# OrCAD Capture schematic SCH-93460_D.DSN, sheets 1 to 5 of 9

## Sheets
1 09. CAN, RF GPO: size C; title: KW47-LOC; rev: D; company: NXP Semiconductors; note: SCH-93460 PDF: SPF-93460; note: 6501 William Cannon Drive West; note: Austin, TX 78735-8598
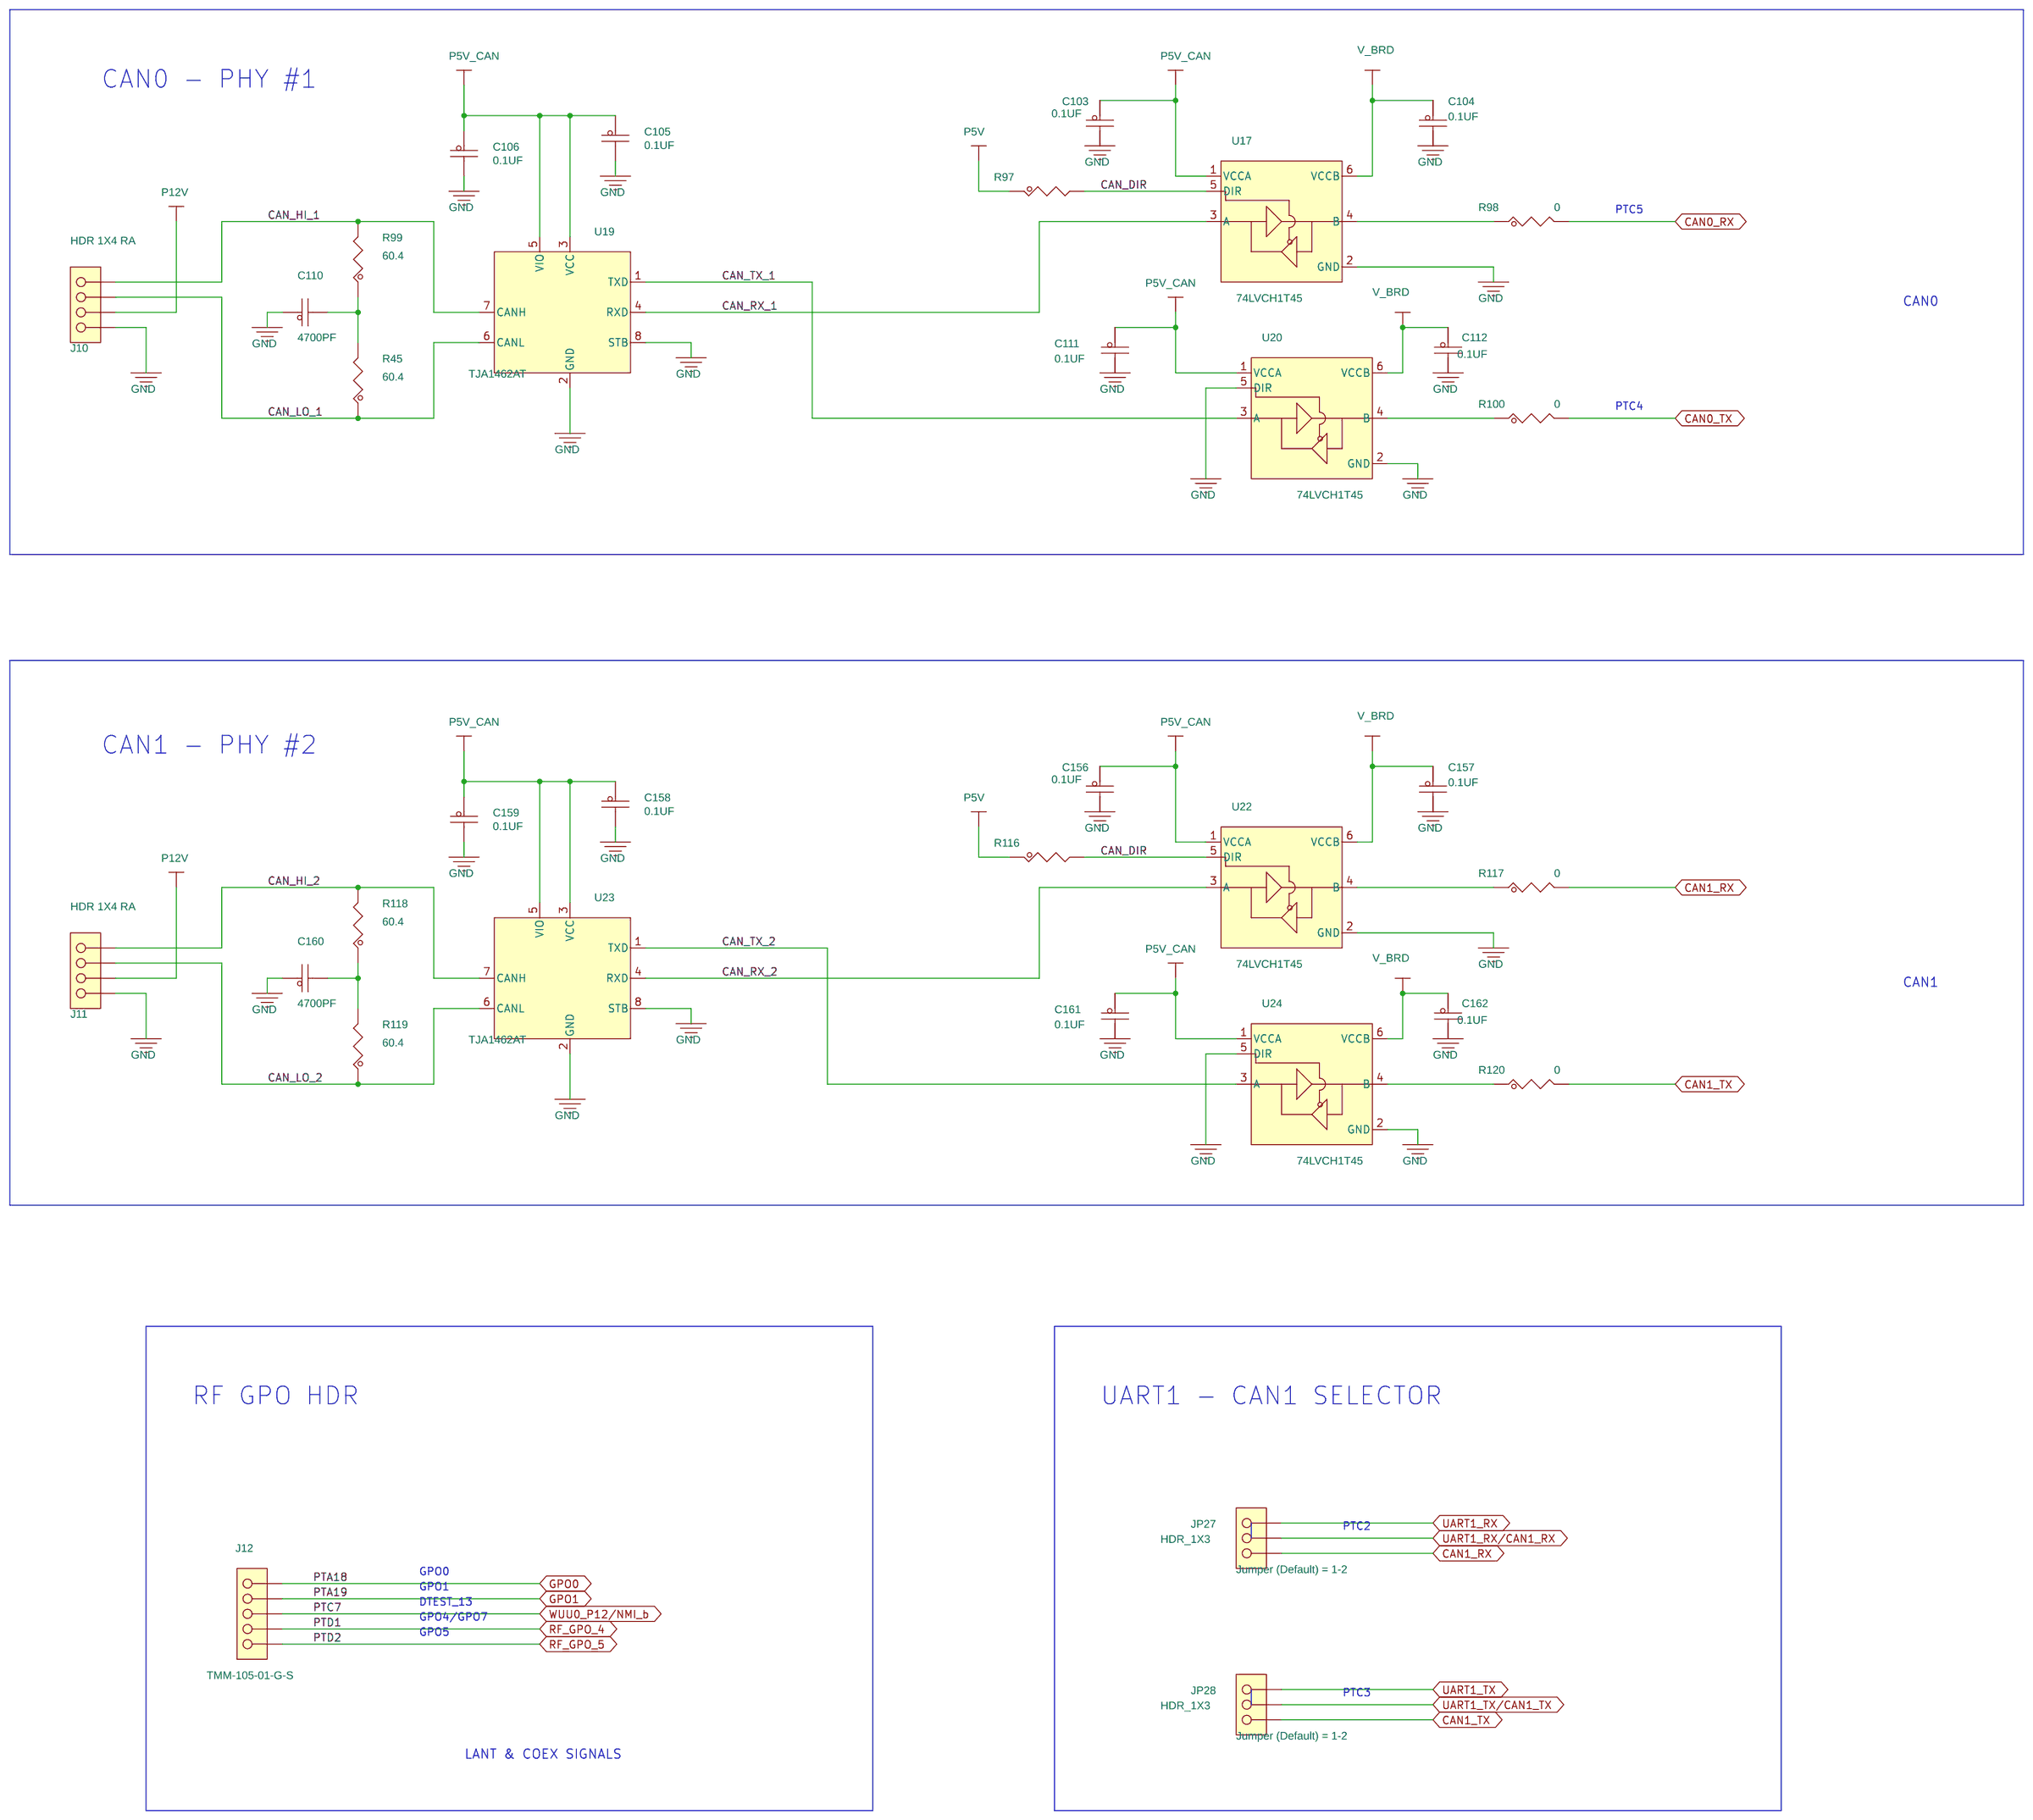
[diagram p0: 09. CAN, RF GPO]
2 01. TITLE PAGE
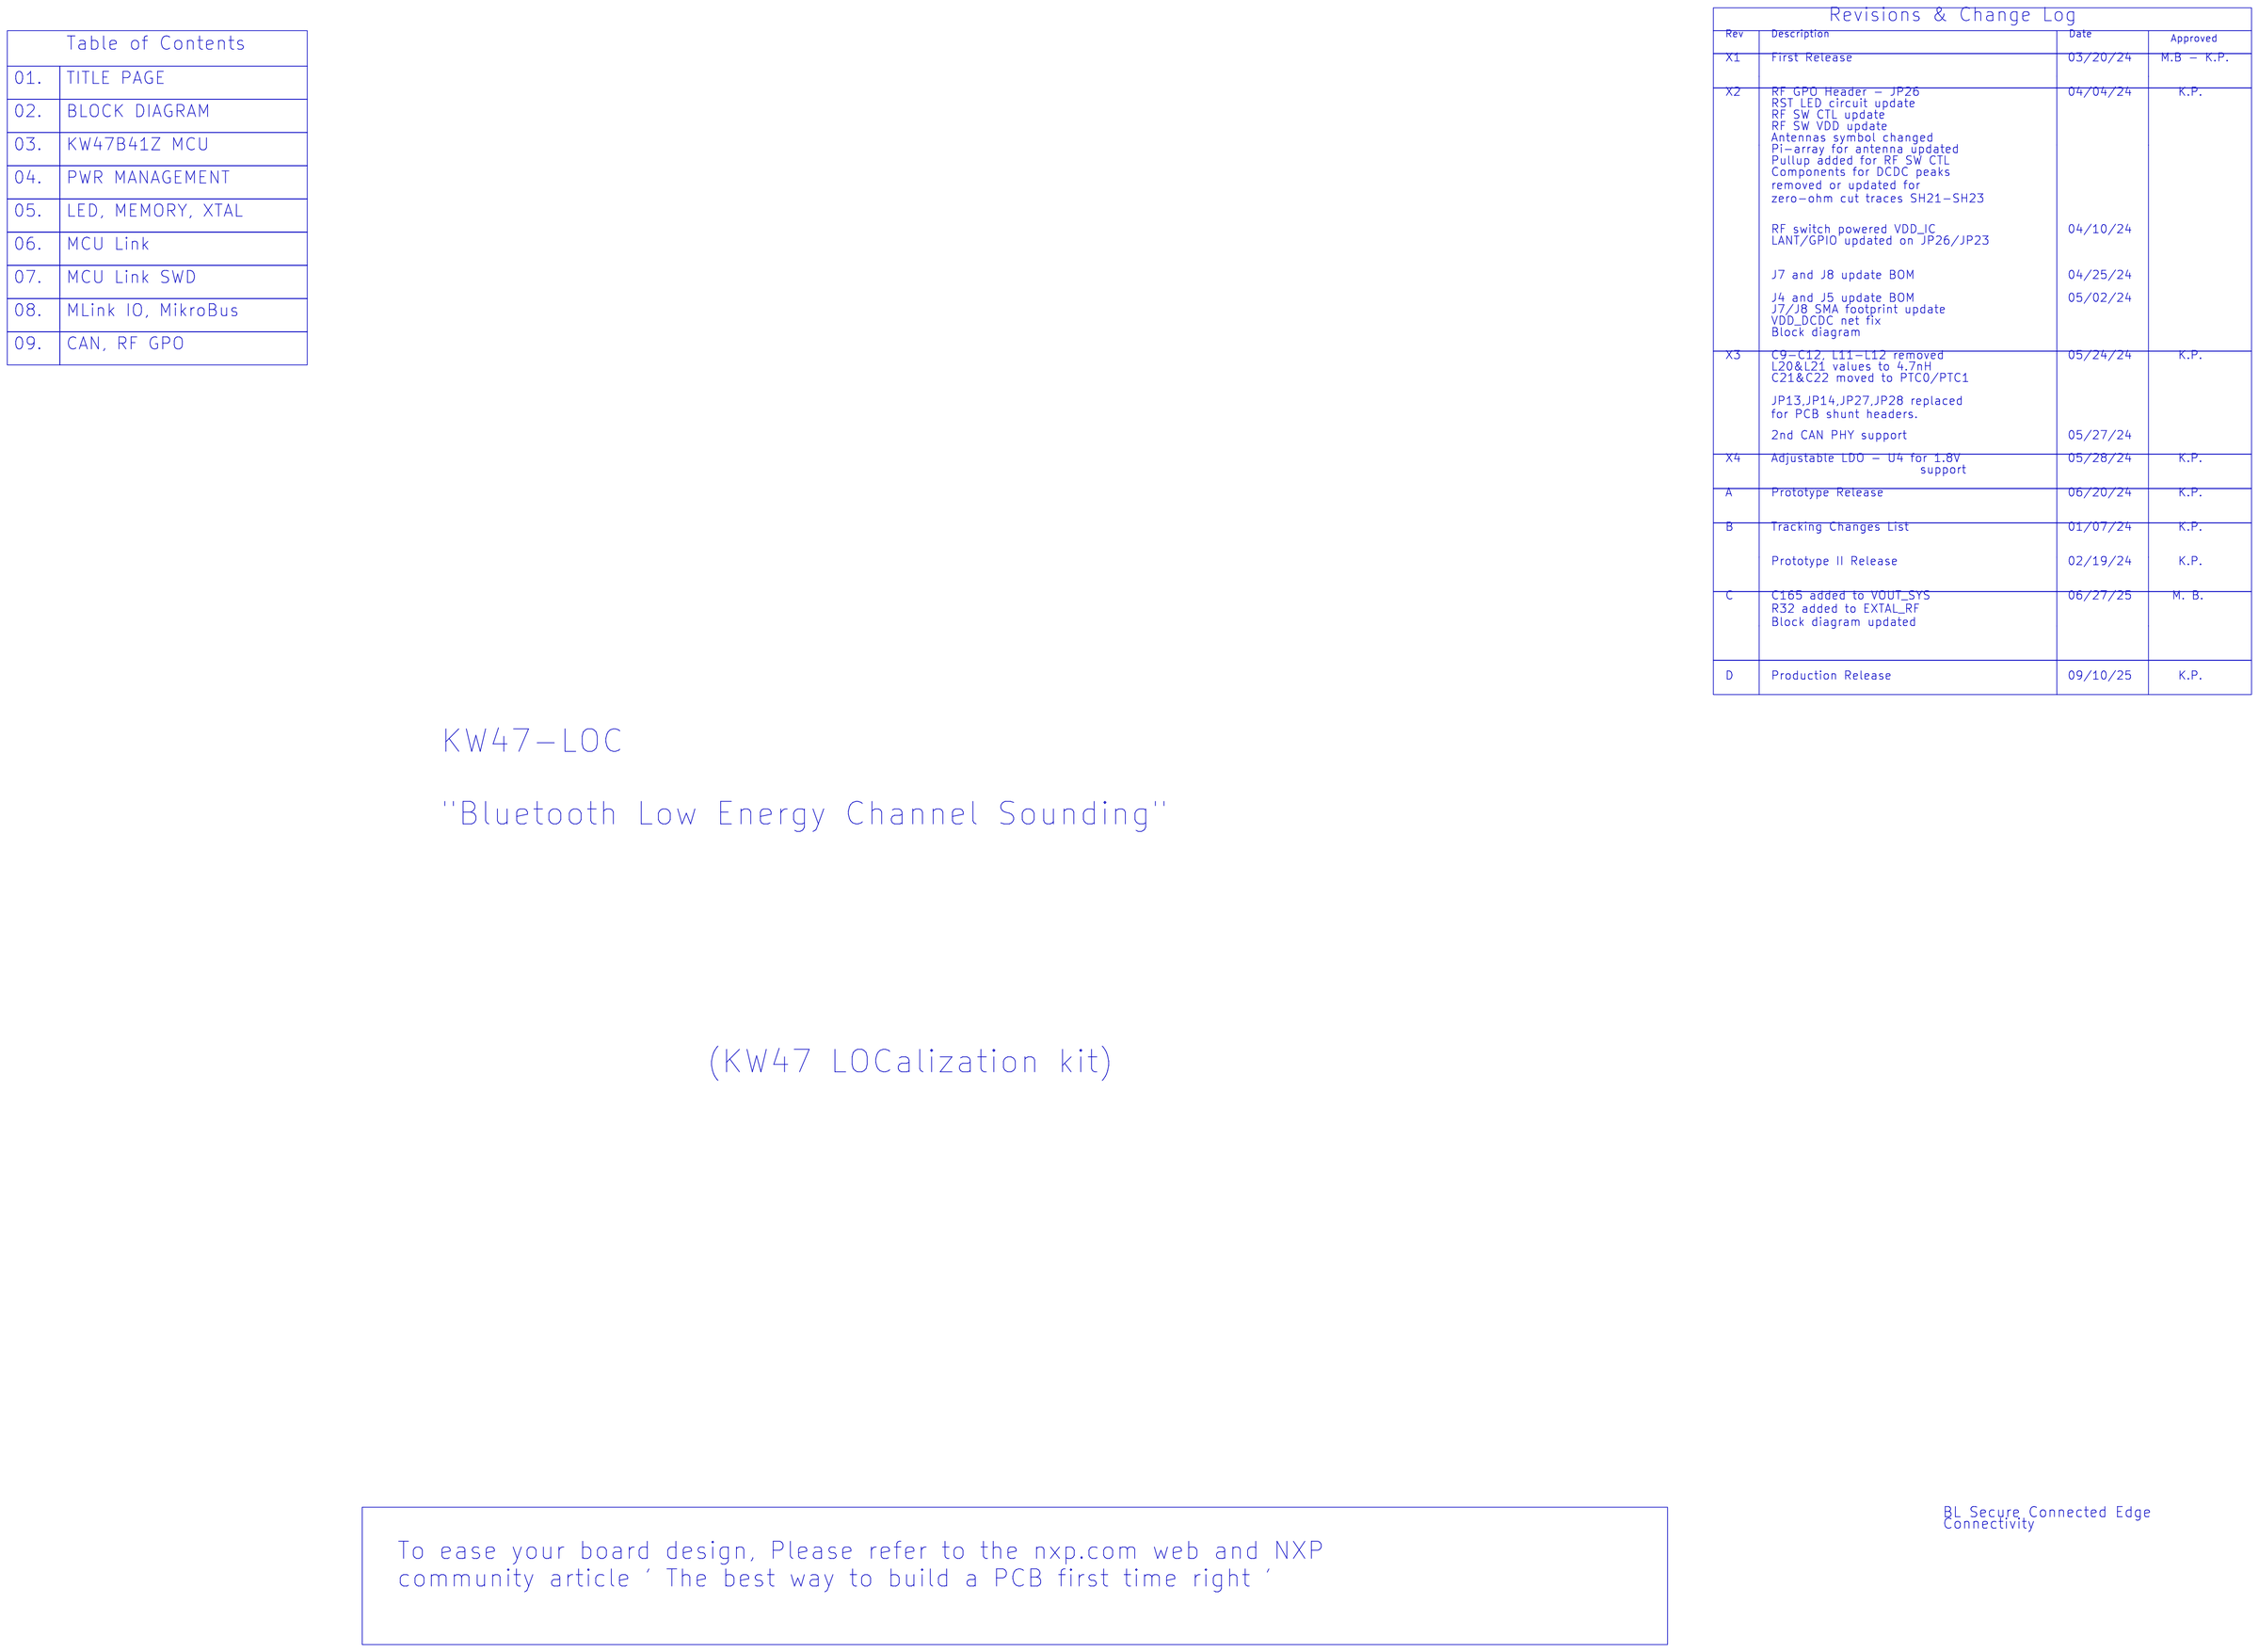
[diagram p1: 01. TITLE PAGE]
3 02. BLOCK DIAGRAM
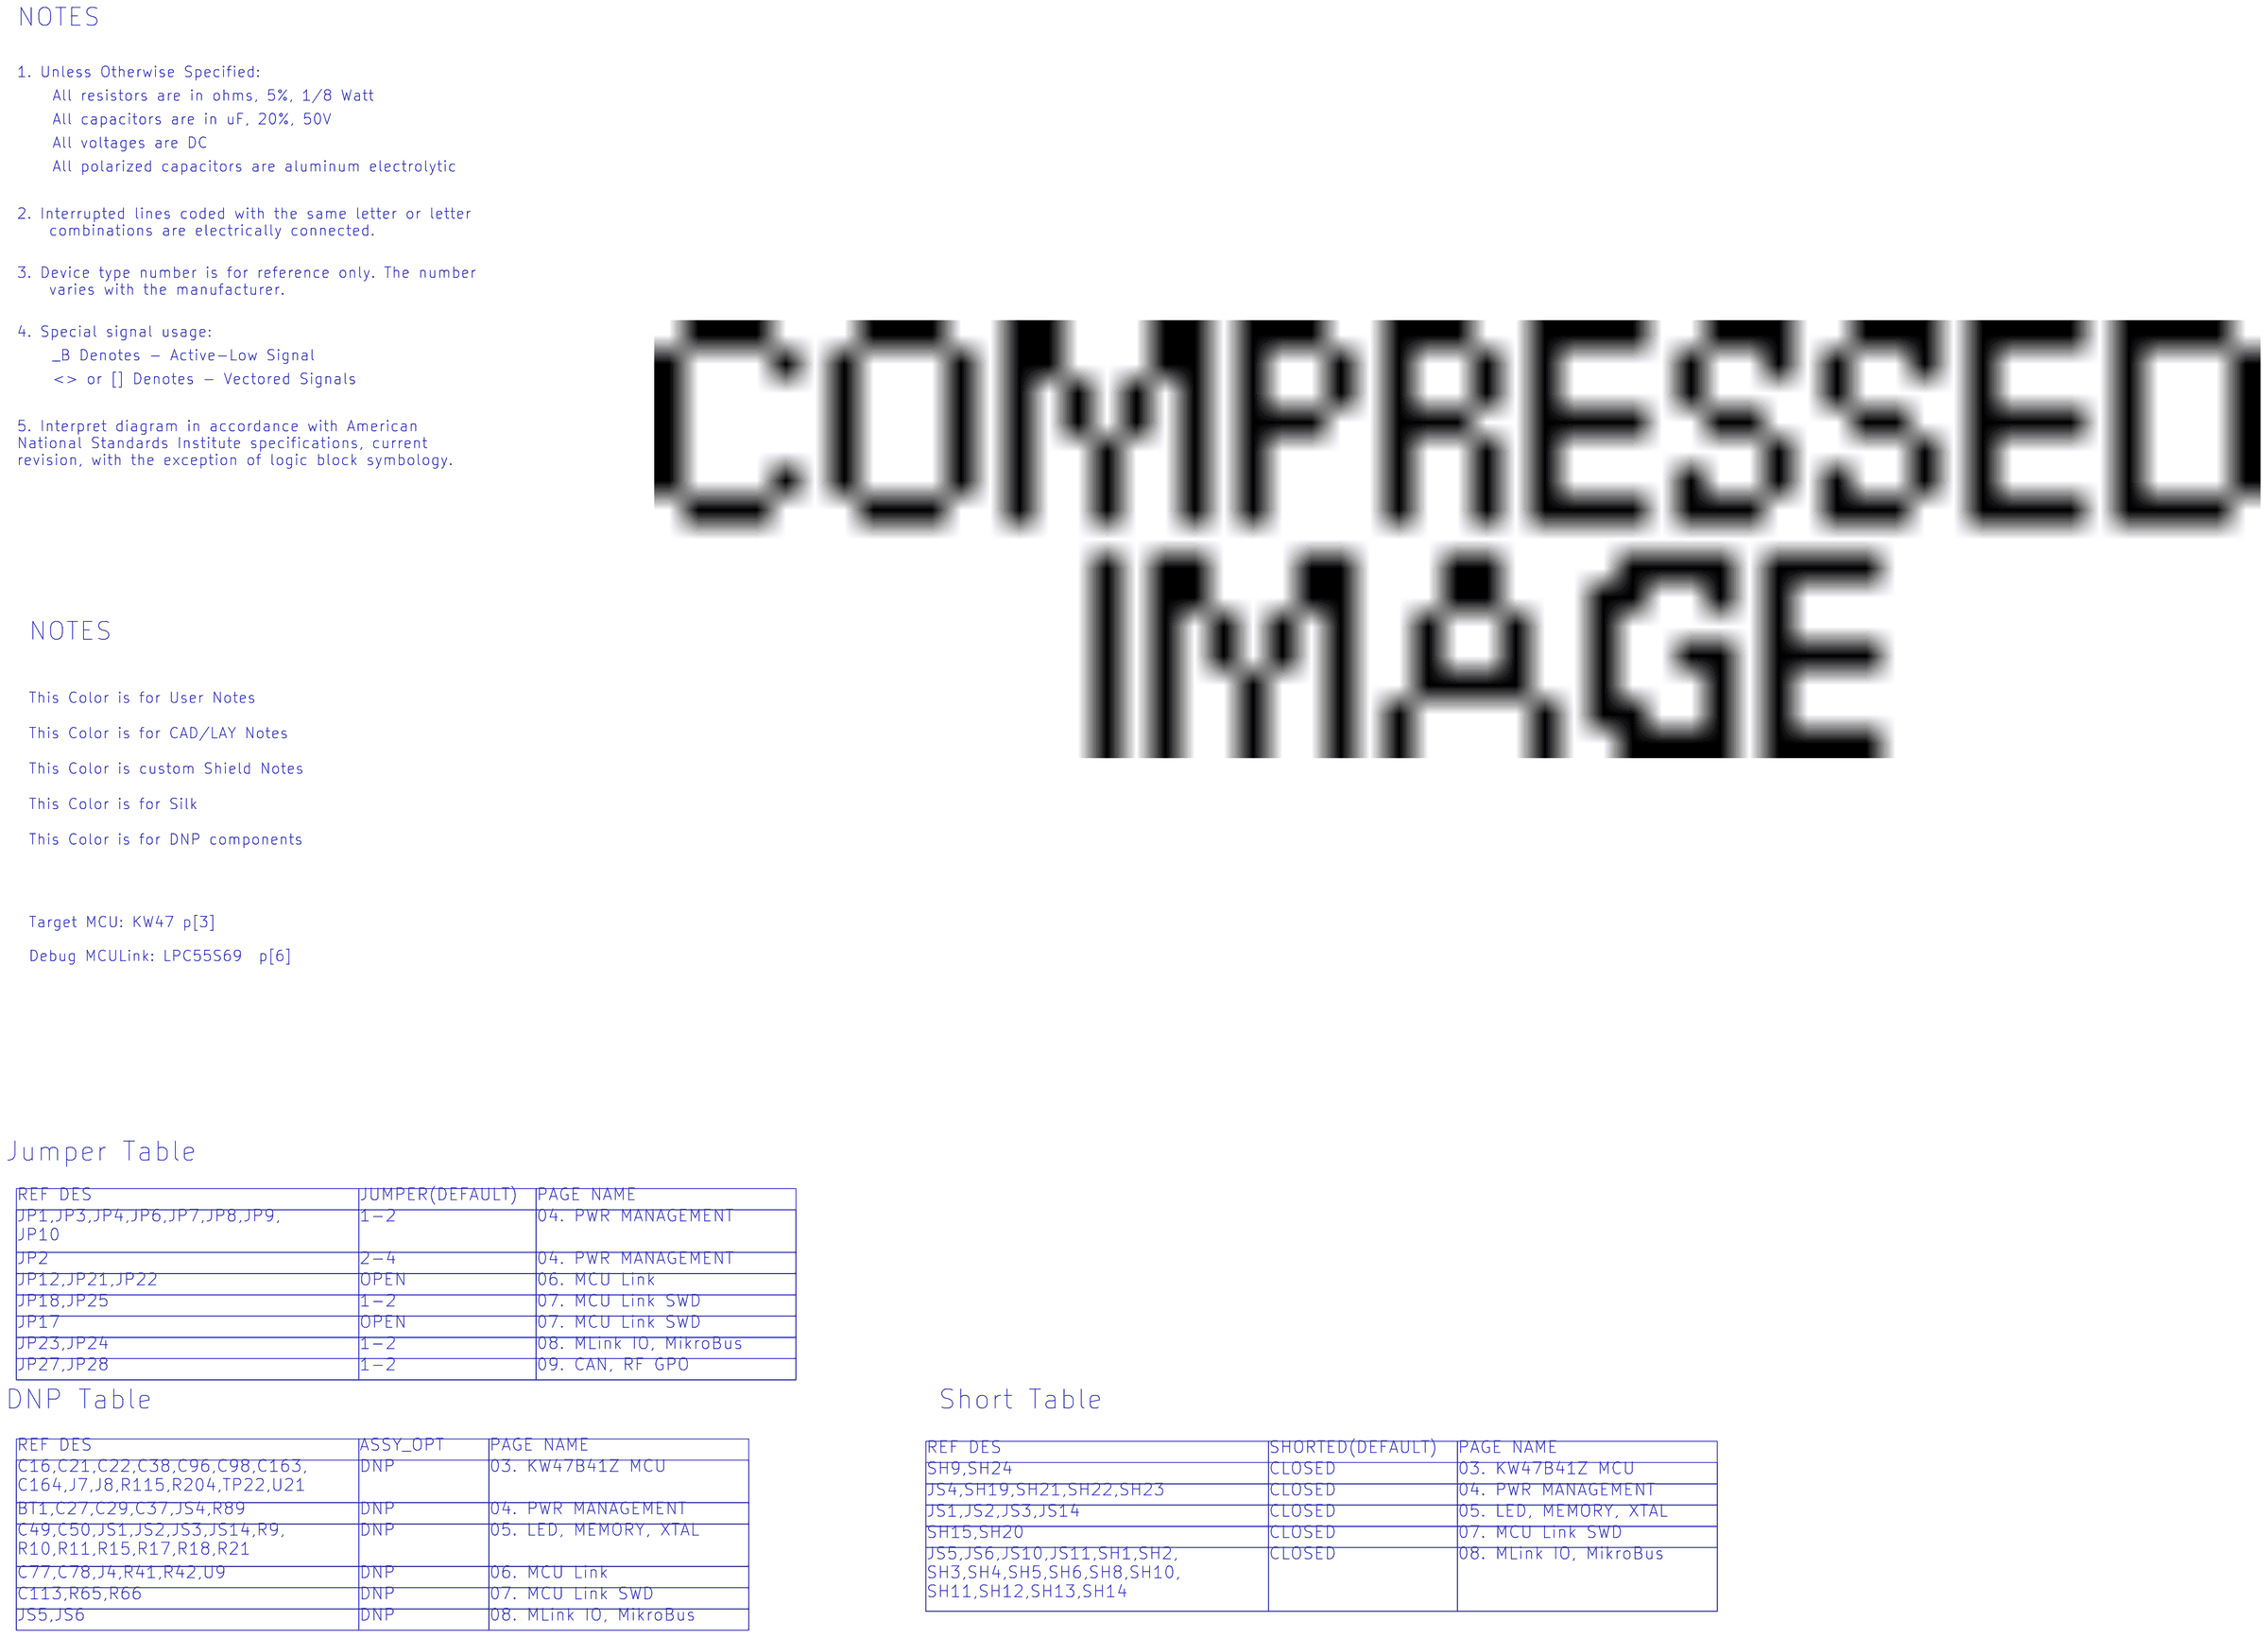
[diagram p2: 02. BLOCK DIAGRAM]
4 03. KW47B41Z MCU: size C
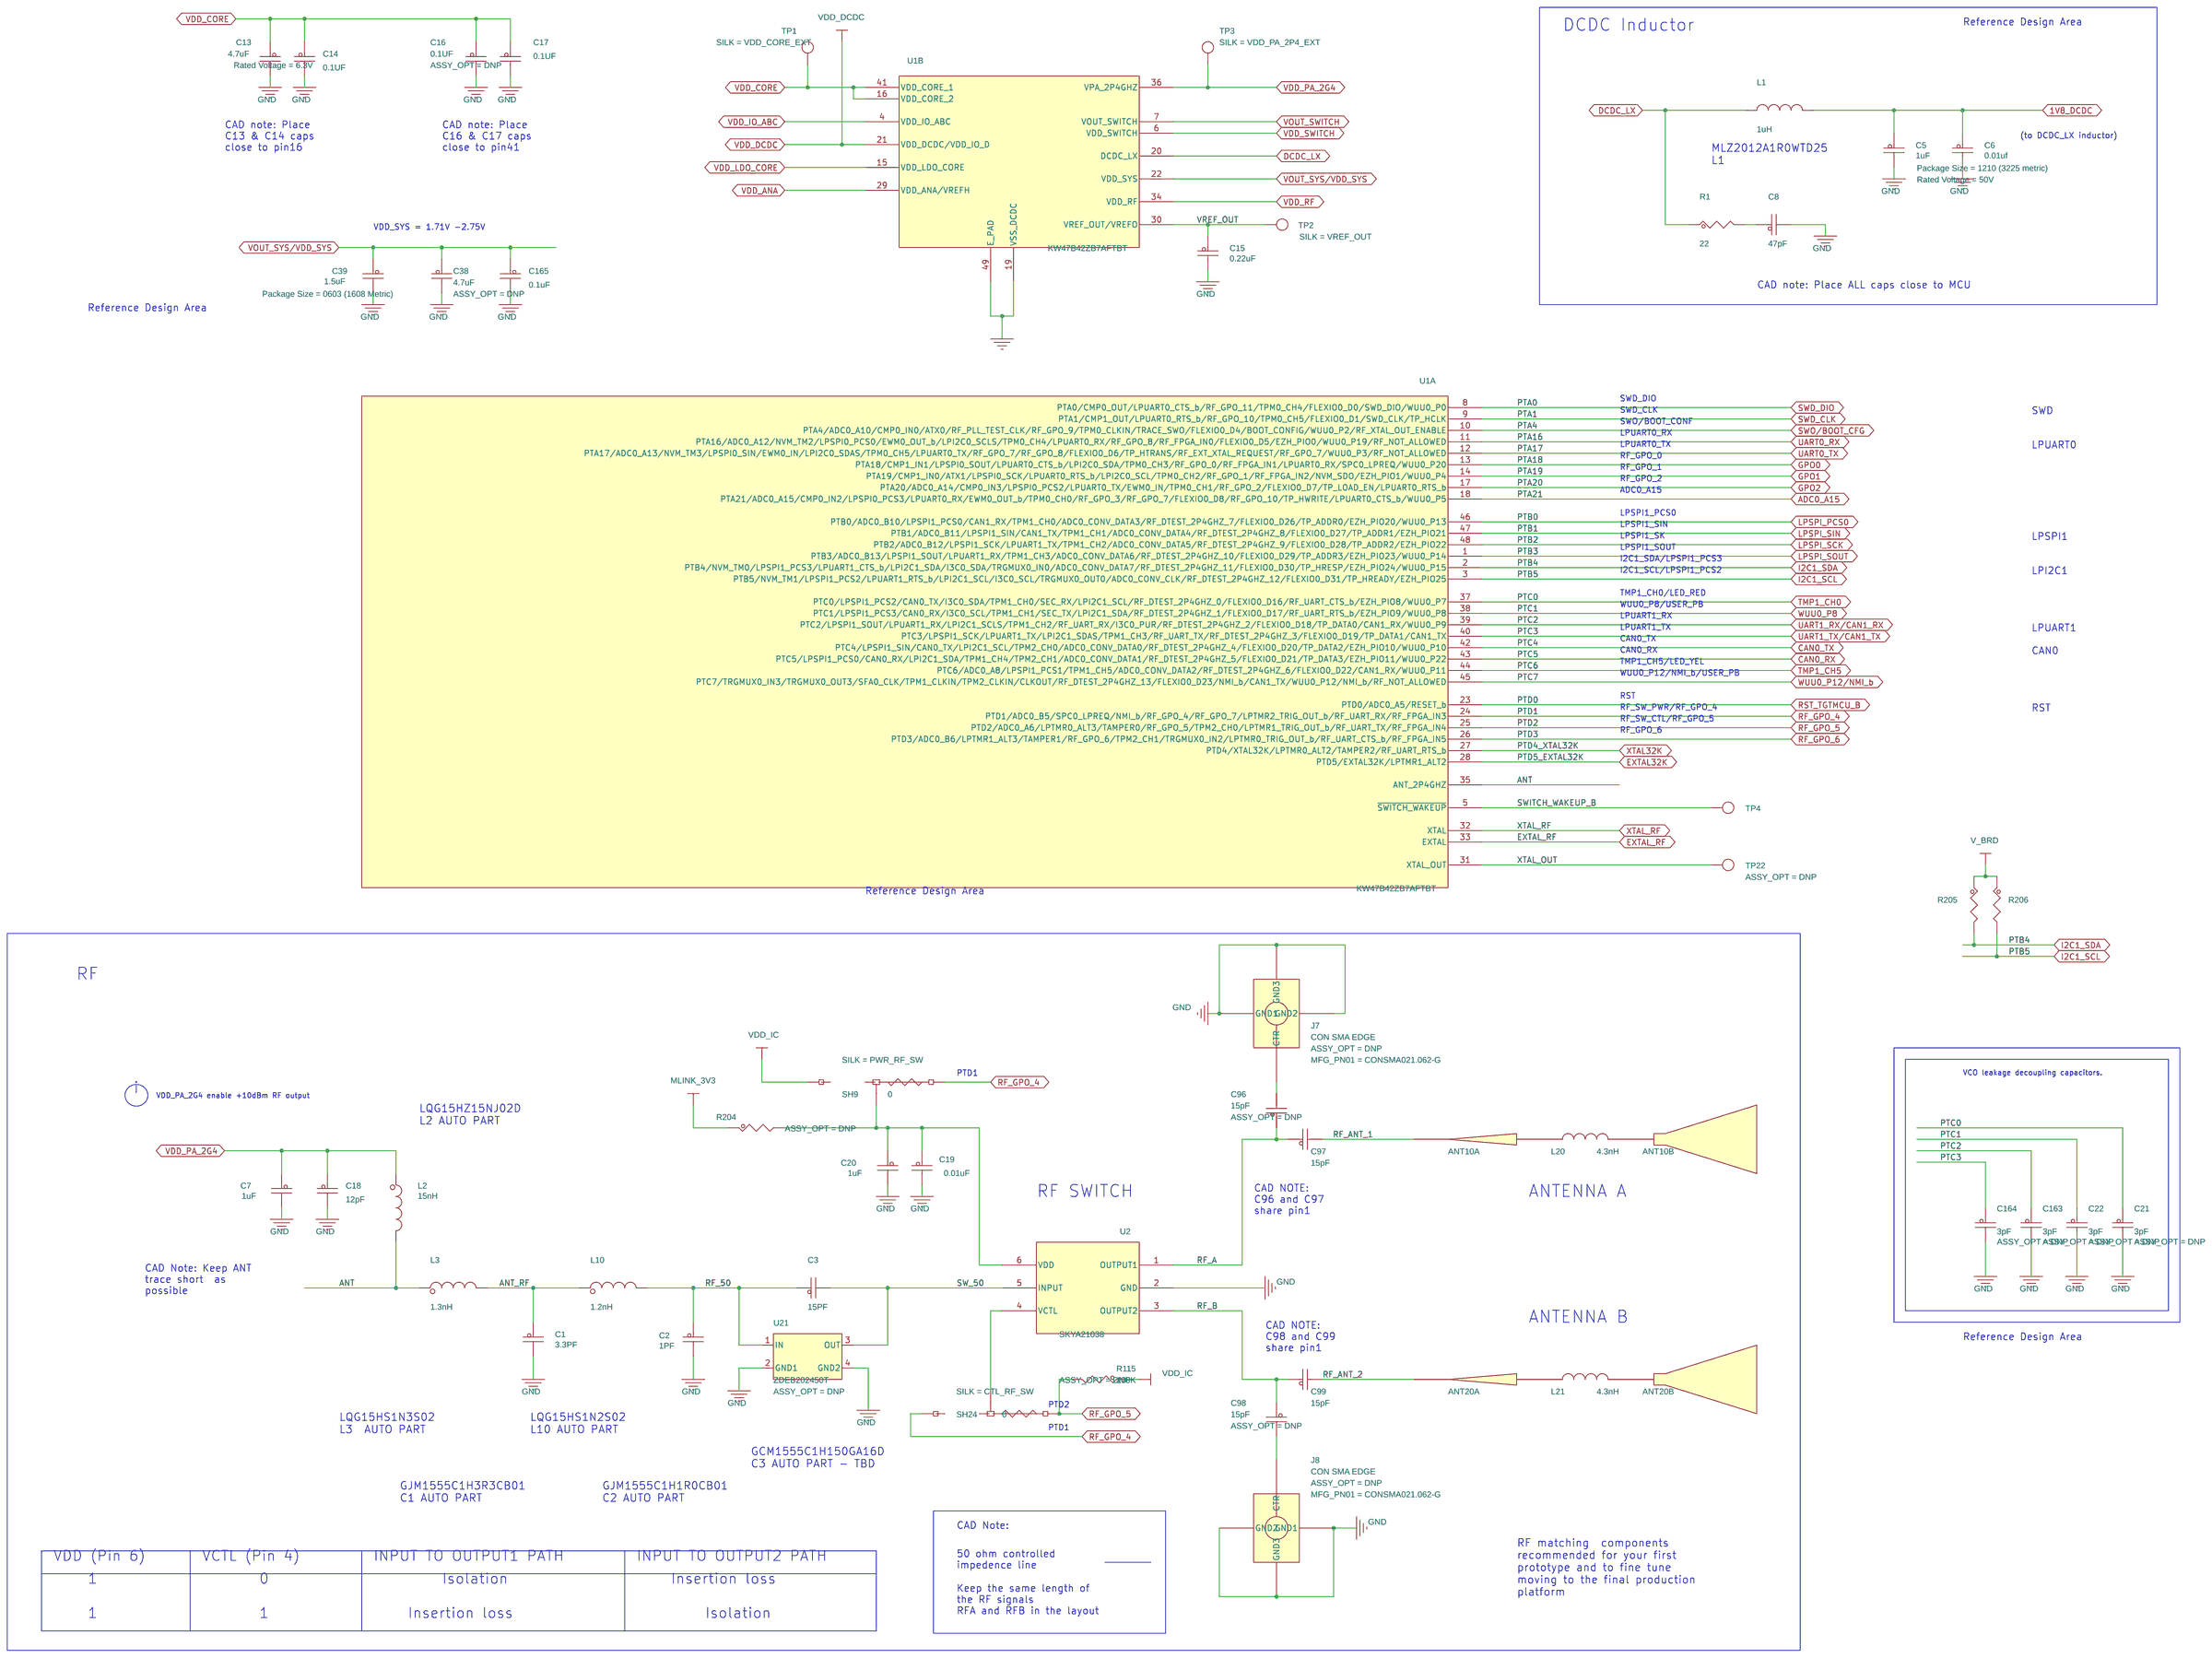
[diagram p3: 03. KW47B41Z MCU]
5 04. PWR MANAGEMENT: size C
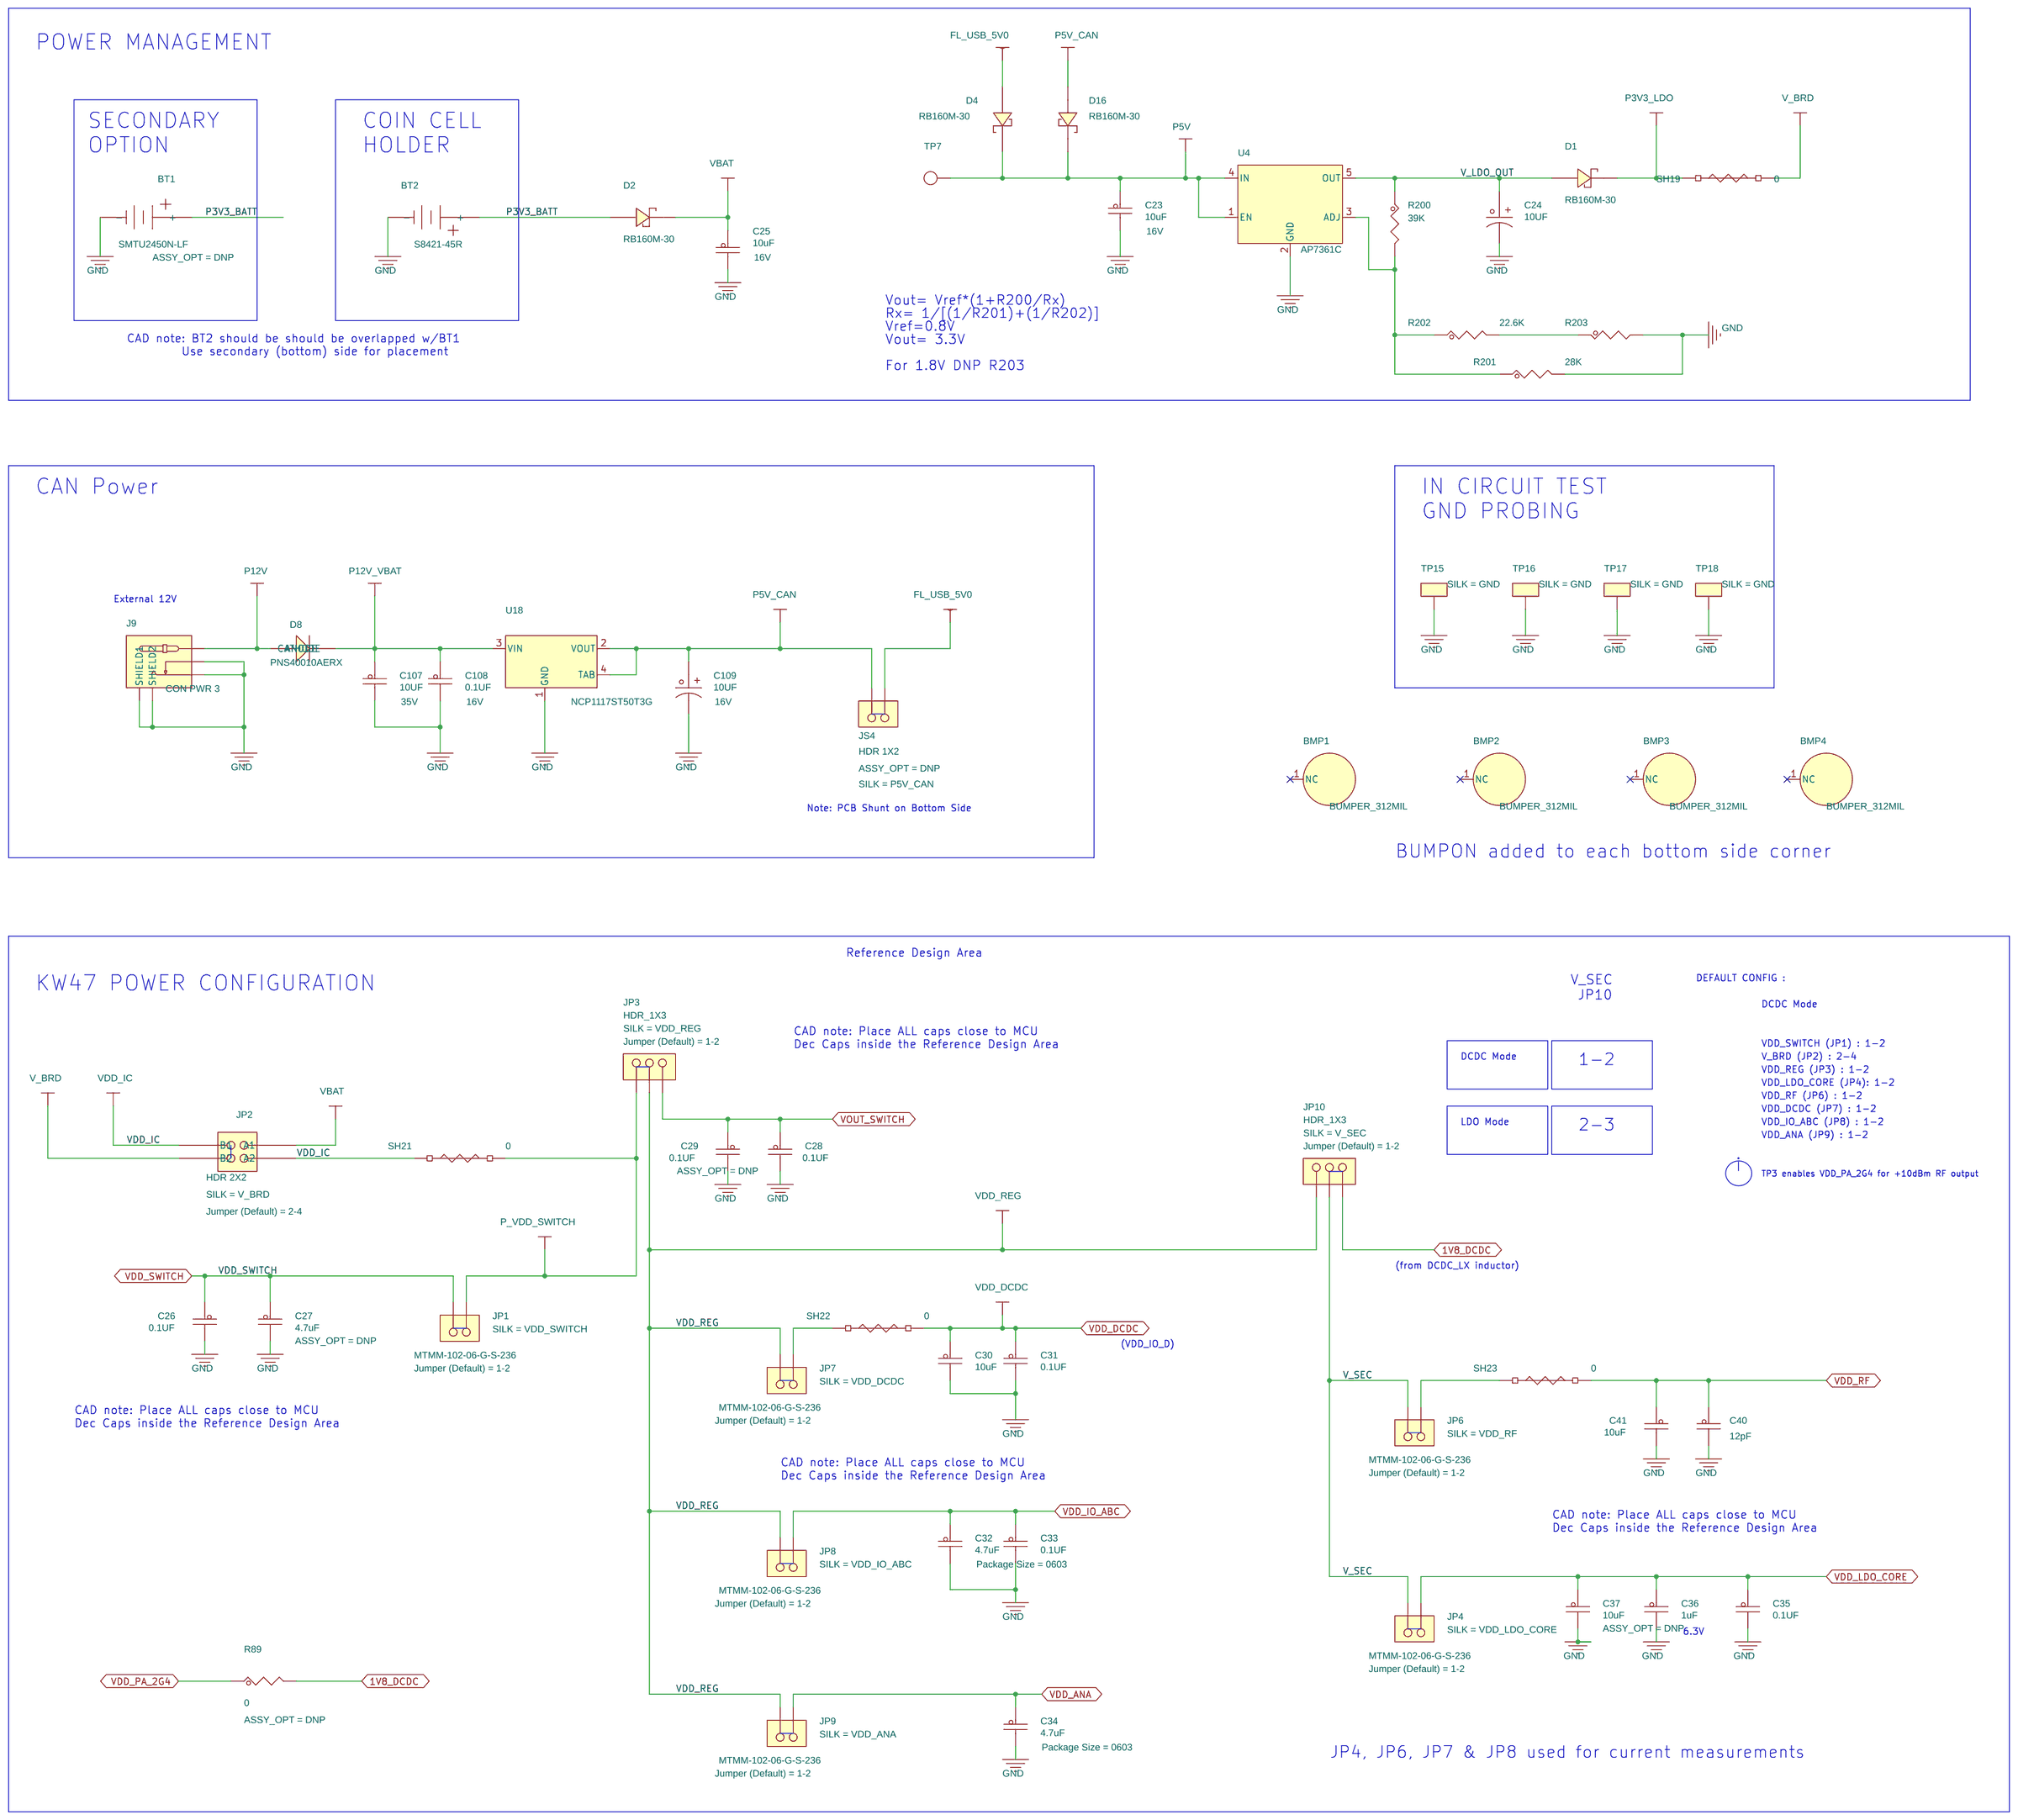
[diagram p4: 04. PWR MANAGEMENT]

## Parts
sheet 03. KW47B41Z MCU
ANT10  F_Antenna  [ANT_KW47_B]  (sections A,B)
ANT20  F_Antenna  [ANT_KW47_B]  (sections A,B)
C1  3.3PF  [CC0402_25]
C2  1PF  [CC0402_25]
C3  15PF  [CC0805_OV]
C5  1uF  [CC1210]
C6  0.01uf  [CC0603_OV]
C7  1uF  [cc0402_tol0p2]
C8  47pF  [CC0402_25]
C13  4.7uF  [cc0402_tol0p2]
C14  0.1UF  [CC0402_25]
C15  0.22uF  [CC0402_25]
C16  0.1UF  [CC0402_25]
C17  0.1UF  [CC0402_25]
C18  12pF  [CC0402_25]
C19  0.01uF  [CC0201]
C20  1uF  [cc0402_tol0p2]
C21  3pF  [CC0402_25]
C22  3pF  [CC0402_25]
C38  4.7uF  [cc0402_tol0p2]
C39  1.5uF  [CC0603_OV]
C96  15pF  [cc0402_alt_nsp]
C97  15pF  [cc0402_alt_nsp]
C98  15pF  [cc0402_alt_nsp]
C99  15pF  [cc0402_alt_nsp]
C163  3pF  [CC0402_25]
C164  3pF  [CC0402_25]
C165  0.1uF  [CC0402_25]
J7  CON SMA EDGE  [CONN_SMA_EDGE_MOUNT_A_KW47]
J8  CON SMA EDGE  [CONN_SMA_EDGE_MOUNT_A_KW47]
L1  1uH  [IND_0805]
L2  15nH  [IND_0402_POL]
L3  1.3nH  [IND_0402_POL]
L10  1.2nH  [IND_0402_POL]
L20  4.3nH  [IND_0402]
L21  4.3nH  [IND_0402]
R1  22  [RC0201]
R115  100K  [RC0402_25]
R204  0  [RC0402_25]
R205  4.7K  [RC0402_25]
R206  4.7K  [RC0402_25]
SH9  0  [SH0603-X2_PIN1TO2]
SH24  0  [SH0603-X2_PIN1TO2]
TP1  TESTLOOP_LP  [test_loop]
TP2  TESTLOOP_LP  [test_loop]
TP3  TESTLOOP_LP  [test_loop]
TP4  TESTLOOP_LP  [test_loop]
TP22  TESTLOOP_BLACK  [tp_th_063]
U1  KW47B42ZB7AFTBT  [qfn_48_0p5_7x7_5p7ep]  (sections A,B)
U2  SKYA21038  [MLPD6_0P35_2EP]
U21  ZDEB202450T  [filter_4_2p1x1p35_sm]
sheet 04. PWR MANAGEMENT
BMP1  BUMPER_312MIL  [bumper_rd_312mil]
BMP2  BUMPER_312MIL  [bumper_rd_312mil]
BMP3  BUMPER_312MIL  [bumper_rd_312mil]
BMP4  BUMPER_312MIL  [bumper_rd_312mil]
BT1  SMTU2450N-LF  [CON2_BH_CR2430]
BT2  S8421-45R  [battery_holder_2032_sm]
C23  10uF  [CC0603_OV]
C24  10UF  [CC3216]
C25  10uF  [CC0603_OV]
C26  0.1UF  [CC0402_25]
C27  4.7uF  [CC0603_OV]
C28  0.1UF  [CC0402_25]
C29  0.1UF  [CC0402_25]
C30  10uF  [CC0603_OV]
C31  0.1UF  [CC0402_25]
C32  4.7uF  [CC0603_OV]
C33  0.1UF  [CC0402_25]
C34  4.7uF  [CC0603_OV]
C35  0.1UF  [CC0402_25]
C36  1uF  [CC0603_OV]
C37  10uF  [CC0603_OV]
C40  12pF  [CC0402_25]
C41  10uF  [CC0603_OV]
C107  10UF  [CC0603_OV]
C108  0.1UF  [CC0402_25]
C109  10UF  [CC3216]
D1  RB160M-30  [pmdu_sod123]
D2  RB160M-30  [pmdu_sod123]
D4  RB160M-30  [pmdu_sod123]
D8  PNS40010AERX  [sod123w]
D16  RB160M-30  [pmdu_sod123]
J9  CON PWR 3  [con3_pwr_jack_th_pj051a]
JP1  MTMM-102-06-G-S-236  [hdr102_tmm]
JP2  HDR 2X2  [hdr202_tmm]
JP3  HDR_1X3  [hdr103_78mil]
JP4  MTMM-102-06-G-S-236  [hdr102_tmm]
JP6  MTMM-102-06-G-S-236  [hdr102_tmm]
JP7  MTMM-102-06-G-S-236  [hdr102_tmm]
JP8  MTMM-102-06-G-S-236  [hdr102_tmm]
JP9  MTMM-102-06-G-S-236  [hdr102_tmm]
JP10  HDR_1X3  [hdr103_78mil]
JS4  HDR 1X2  [sh_hdr102_2mm_bottom]
R89  0  [RC0603_OV]
R200  39K  [RC0402_25]
R201  28K  [RC0402_25]
R202  22.6K  [RC0402_25]
R203  0  [RC0402_25]
SH19  0  [SH0603]
SH21  0  [SH0402]
SH22  0  [SH0402]
SH23  0  [SH0402]
TP7  TPAD_040  [TPAD_040]
TP15  TP_2P7X4P7  [tp_2p7x4p7mm]
TP16  TP_2P7X4P7  [tp_2p7x4p7mm]
TP17  TP_2P7X4P7  [tp_2p7x4p7mm]
TP18  TP_2P7X4P7  [tp_2p7x4p7mm]
U4  AP7361C  [sot-89-5]
U18  NCP1117ST50T3G  [sot223]
sheet 09. CAN, RF GPO
C103  0.1UF  [CC0402_25]
C104  0.1UF  [CC0402_25]
C105  0.1UF  [CC0402_25]
C106  0.1UF  [CC0402_25]
C110  4700PF  [CC0603_OV]
C111  0.1UF  [CC0402_25]
C112  0.1UF  [CC0402_25]
C156  0.1UF  [CC0402_25]
C157  0.1UF  [CC0402_25]
C158  0.1UF  [CC0402_25]
C159  0.1UF  [CC0402_25]
C160  4700PF  [CC0603_OV]
C161  0.1UF  [CC0402_25]
C162  0.1UF  [CC0402_25]
J10  HDR 1X4 RA  [con_hdr_4m_100_th_ra]
J11  HDR 1X4 RA  [con_hdr_4m_100_th_ra]
J12  TMM-105-01-G-S  [hdr105_5m_79_th]
JP27  HDR_1X3  [hdr103_78mil]
JP28  HDR_1X3  [hdr103_78mil]
R45  60.4  [RC0805_OV]
R97  4.7K  [RC0402_25]
R98  0  [RC0402_25]
R99  60.4  [RC0805_OV]
R100  0  [RC0402_25]
R116  4.7K  [RC0402_25]
R117  0  [RC0402_25]
R118  60.4  [RC0805_OV]
R119  60.4  [RC0805_OV]
R120  0  [RC0402_25]
U17  74LVCH1T45  [udfn6_1x1p5mm]
U19  TJA1462AT  [SO8_1P27_4X5]
U20  74LVCH1T45  [udfn6_1x1p5mm]
U22  74LVCH1T45  [udfn6_1x1p5mm]
U23  TJA1462AT  [SO8_1P27_4X5]
U24  74LVCH1T45  [udfn6_1x1p5mm]

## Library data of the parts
ANT10 ANT20 = ant_monopole: PCB F ANTENNA, NO PART ORDER; AGILE_PN: 510-75678; CAD_APPROVED: Yes; HEIGHT: 0; MFG_NAME01: NOT A PART; MFG_PN01: NOT A PART; ROHS: Yes
C1 = CAP_NP: CAP CER 3.3pF 50V 7.58% C0G HIGH-Q 0402; AGILE_PN: 150-79956; CAD_APPROVED: Yes; HEIGHT: 0.55; MFG_NAME01: MURATA; MFG_PN01: GJM1555C1H3R3CB01D; Package Size: 0402; ROHS: Yes; Rated Voltage: 50V; Temp Range: -55C to +125C; Tolerance: 0.25PF
C2 = CAP_NP: CAP CER 1.0PF 50V +/-0.25PF C0G RF HIGH Q 0402; AGILE_PN: 150-75486; CAD_APPROVED: Yes; HEIGHT: .55; MFG_NAME01: MURATA; MFG_PN01: GJM1555C1H1R0CB01D; Package Size: 0402; Package Type: SMD; ROHS: Yes; Rated Voltage: 50V; Temp Range: -55C to +125C; Tolerance: 0.25pF
C3 = CAP_NP: CAP CER 15PF 50V 5% C0G 0805; AGILE_PN: 150-75034; CAD_APPROVED: Yes; HEIGHT: 0.95; MFG_NAME01: KEMET; MFG_PN01: C0805C150J5GAC; Package Size: 0805; Package Type: Tape & reel; ROHS: Yes; Rated Voltage: 50V; Temp Range: -55C to +125C; Tolerance: 5%
C5 = CAP_NP: CAP CER 1uF 50V 10% X7R  AEC-Q200 1210; AGILE_PN: 150-80805; CAD_APPROVED: Yes; HEIGHT: 1.7; MFG_NAME01: KEMET; MFG_PN01: C1210C105K5RACAUTO; Package Size: 1210 (3225 metric); Package Type: SMD/SMT; ROHS: Yes; Rated Voltage: 50V; Temp Range: -55C to +125C; Tolerance: 10%
C6 = CAP_NP: CAP CER 0.01uF 50V 10% X7R AEC-Q200 0603; AGILE_PN: 150-79361; CAD_APPROVED: Yes; FPLIST: CC0603_OV,CC0603,0603_CC; HEIGHT: 0.9; MFG_NAME01: TDK; MFG_PN01: CGA3E2X7R1H103K080AA; Package Size: 0603; Package Type: 7; ROHS: Yes; Rated Voltage: 50V; Temp Range: -55C to +125C; Tolerance: 10%; VOLTAGE: 50V
C7 C20 = CAP_NP: CAP CER 1uF 10V 10% X7S AEC-Q200 0402; AGILE_PN: 150-79497; CAD_APPROVED: Yes; FPLIST: cc0402_tol0p2,cc0402_tol0p2_ov,cc0402_25_tol0p2,0402_cc_nsp; HEIGHT: 0.7MM; MFG_NAME01: MURATA; MFG_PN01: GCM155C71A105KE38D; Package Size: 0402; ROHS: NULL; Rated Voltage: 10V; Temp Range: -55C to +125C; Tolerance: 10%; VOLTAGE: 10V
C8 = CAP_NP: CAP CER 47pF 50V 5% C0G AEC-Q200 0402; AGILE_PN: 150-79041; CAD_APPROVED: Yes; HEIGHT: 0.55MM; MFG_NAME01: MURATA; MFG_PN01: GCM1555C1H470JA16; Package Size: 0402; ROHS: NULL; Rated Voltage: 50V; Temp Range: -55C to +125C; Tolerance: 5%; VOLTAGE: 50V
C13 = CAP_NP: CAP CER 4.7uF 6.3V 10% X7T AEC-Q200 0402; 3D_Mechanical_Footprint_File: http://fcl.am.freescale.net/ALLEGRO/step/cc0402_tol0p2.STEP; AGILE_PN: 150-81914; CAD_APPROVED: Yes; HEIGHT: 0.7; MFG_NAME01: KYOCERA AVX; MFG_PN01: KAM05CT70J475KH; Package Size: 0402 (1005 Metric); Package Type: Surface Mount, MLCC; ROHS: Yes; Rated Voltage: 6.3V; Tolerance: 10%
C14 C17 = CAP_NP: CAP CER 0.1UF 16V 10% X7R 0402; 3D_Mechanical_Footprint_File: http://fcl.am.freescale.net/ALLEGRO/step/cc0402_25.STEP; AGILE_PN: 150-75182; CAD_APPROVED: Yes; FPLIST: CC0402_25,CC0402_HD,0402_CC,CAPC0402_L,cc0402_lamp3; HEIGHT: 0.635mm; MFG_NAME01: KEMET; MFG_PN01: C0402C104K4RACTU; ROHS: NULL; Rated Voltage: 16V; Temp Range: -55C to +125C; Tolerance: 10%
C15 = CAP_NP: CAP CER 0.22uF 16V 10% X7R AEC-Q200 0402; 3D_Mechanical_Footprint_File: http://fcl.am.freescale.net/ALLEGRO/step/cc0402_25.STEP; AGILE_PN: 150-79207; CAD_APPROVED: Yes; FPLIST: CC0402_25,CC0402_HD,0402_CC,capc0402_l; HEIGHT: 0.55MM; MFG_NAME01: MURATA; MFG_PN01: GCM155R71C224KE02; Package Type: 0402; ROHS: NULL; Rated Voltage: 16V; Temp Range: -55C to +125C; Tolerance: 10%; VOLTAGE: 16V
C16 = CAP_NP: CAP CER 0.1UF 16V 10% X7R 0402; 3D_Mechanical_Footprint_File: http://fcl.am.freescale.net/ALLEGRO/step/cc0402_25.STEP; AGILE_PN: 150-75182; ASSY_OPT: DNP; CAD_APPROVED: Yes; FPLIST: CC0402_25,CC0402_HD,0402_CC,CAPC0402_L,cc0402_lamp3; HEIGHT: 0.635mm; MFG_NAME01: KEMET; MFG_PN01: C0402C104K4RACTU; ROHS: NULL; Rated Voltage: 16V; Temp Range: -55C to +125C; Tolerance: 10%
C18 C40 = CAP_NP: CAP CER 12pF 50V 5% C0G AEC-Q200 0402; AGILE_PN: 150-80457; CAD_APPROVED: Yes; FPLIST: CC0402_25,CC0402_HD,0402_CC,capc0402_l; HEIGHT: 0.55MM; MFG_NAME01: MURATA; MFG_PN01: GCM1555C1H120JA16D; Package Size: 0402; ROHS: NULL; Rated Voltage: 50V; Temp Range: -55C to +125C; Tolerance: 5%; VOLTAGE: 50V
C19 = CAP_NP: CAP CER 0.01uF 16V 10% X7R 0201; 3D_Mechanical_Footprint_File: http://fcl.am.freescale.net/ALLEGRO/step/cc0201.STEP; AGILE_PN: 150-80313; CAD_APPROVED: Yes; HEIGHT: 0.33mm; MFG_NAME01: MURATA; MFG_PN01: GRM033R71C103KE14D; Package Size: 0201 (0603 Metric); ROHS: NULL; Rated Voltage: 16V; Temp Range: -55°C to +125°C; Tolerance: ±10%; VOLTAGE: 16V
C21 C22 C163 C164 = CAP_NP: CAP CER 3pF 50V ±0.25pF C0G AEC-Q200 0402; AGILE_PN: 150-80781; ASSY_OPT: DNP; CAD_APPROVED: YES; FPLIST: CC0402_25,CC0402_HD,0402_CC; HEIGHT: 0.55; MFG_NAME01: Murata Electronics; MFG_PN01: GCQ1555C1H3R0CB01D; Package Size: 0402 (1005 Metric); Package Type: Surface Mount, MLCC; ROHS: YES; Rated Voltage: 50V; Temp Range: -55C to +125C; Tolerance: 0.25pF
C38 = CAP_NP: CAP CER 4.7uF 6.3V 10% X7T AEC-Q200 0402; 3D_Mechanical_Footprint_File: http://fcl.am.freescale.net/ALLEGRO/step/cc0402_tol0p2.STEP; AGILE_PN: 150-81914; ASSY_OPT: DNP; CAD_APPROVED: Yes; HEIGHT: 0.7; MFG_NAME01: KYOCERA AVX; MFG_PN01: KAM05CT70J475KH; Package Size: 0402 (1005 Metric); Package Type: Surface Mount, MLCC; ROHS: Yes; Rated Voltage: 6.3V; Tolerance: 10%
C39 = CAP_NP: CAP CER 1.5uF 6.3V 10% X7R AEC-Q200 0603; 3D_Mechanical_Footprint_File: http://fcl.am.freescale.net/ALLEGRO/step/cc0603_ov.STEP; AGILE_PN: 150-81694; HEIGHT: 0.90; MFG_NAME01: TDK Corporation; MFG_PN01: CGA3E1X7R0J155K080AC; Package Size: 0603 (1608 Metric); Package Type: Surface Mount, MLCC; ROHS: Yes; Rated Voltage: 6.3V; Temp Range: -55 °C to +125 °C; Tolerance: 10%
C96 C98 = CAP_NP: CAP CER 15pF 50V 2% C0G AEC-Q200 0402; AGILE_PN: 150-80746; ASSY_OPT: DNP; CAD_APPROVED: Yes; HEIGHT: 0.55MM; MFG_NAME01: MURATA; MFG_PN01: GCM1555C1H150GA16D; Package Size: 0402; Package Type: SMD; ROHS: NULL; Rated Voltage: 50V; Temp Range: -55C to +125C; Tolerance: 2%; VOLTAGE: 50V
C97 C99 = CAP_NP: CAP CER 15pF 50V 2% C0G AEC-Q200 0402; AGILE_PN: 150-80746; CAD_APPROVED: Yes; HEIGHT: 0.55MM; MFG_NAME01: MURATA; MFG_PN01: GCM1555C1H150GA16D; Package Size: 0402; Package Type: SMD; ROHS: NULL; Rated Voltage: 50V; Temp Range: -55C to +125C; Tolerance: 2%; VOLTAGE: 50V
C165 = CAP_NP: CAP CER 0.1uF 16V 10% X7R AEC-Q200 0402; AGILE_PN: 150-79025; CAD_APPROVED: Yes; FPLIST: CC0402_25,CC0402_HD,0402_CC,capc0402_l; HEIGHT: 0.55MM; MFG_NAME01: MURATA; MFG_PN01: GCM155R71C104KA55D; Package Size: 0402; Package Type: ø180mm Reel PAPER; ROHS: NULL; Rated Voltage: 16V; Temp Range: -55C to +125C; Tolerance: 10%
J7 J8 = CONN_SMA_EDGE_4P: CON 1 SKT JACK SMA EDGE MOUNT 62MIL BOARD SMT 50 OHM -- AU; 3D_Mechanical_Footprint_File: http://fcl.am.freescale.net/ALLEGRO/step/conn_sma_edge_mount_a.step; AGILE_PN: 211-10308; ASSY_OPT: DNP; CAD_APPROVED: Yes; HEIGHT: 3.4mm; MFG_NAME01: TE Connectivity Ltd; MFG_PN01: CONSMA021.062-G; ROHS: NULL; Temp Range: -65°C to +165°C
L1 = INDUCTOR: IND CHK 1UH@10MHz 900MA 20%  AEC-Q200 0805; 3D_Mechanical_Footprint_File: http://fcl.am.freescale.net/ALLEGRO/step/ind_0805.STEP; AGILE_PN: 180-80855; CAD_APPROVED: Yes; HEIGHT: 1.05MM; MFG_NAME01: TDK Corporation; MFG_PN01: MLZ2012A1R0WTD25; Package Size: 0805 (2012 Metric); ROHS: NULL; Temp Range: -55 to +125C
L2 = INDP: IND -- 15nH@100MHz 450mA 5% AEC-Q200 0402; AGILE_PN: 180-80565; CAD_APPROVED: Yes; FPLIST: IND_0402_POL,0402_CC_POL; HEIGHT: 0.55MM; MFG_NAME01: MURATA; MFG_PN01: LQG15HZ15NJ02D; Package Size: 0402 (1005 Metric); ROHS: NULL; Temp Range: -55C to +125C
L3 = INDP: IND -- 1.3nH@100MHz 1A 23.08% 0.07 OHM 0402; 3D_Mechanical_Footprint_File: http://fcl.am.freescale.net/ALLEGRO/step/ind_0402_pol.STEP; AGILE_PN: 180-10204; CAD_APPROVED: Yes; HEIGHT: 0.55mm; MFG_NAME01: Murata; MFG_PN01: LQG15HS1N3S02D; ROHS: NULL; Temp Range: -55°C to +125°C
L10 = INDP: IND AIR 1.2nH@100MHZ 1A 0.07 OHM 25% 0402; 3D_Mechanical_Footprint_File: http://fcl.am.freescale.net/ALLEGRO/step/ind_0402_pol.STEP; AGILE_PN: 180-10205; CAD_APPROVED: Yes; HEIGHT: 0.55mm; MFG_NAME01: MURATA; MFG_PN01: LQG15HS1N2S02D; Package Size: 0402 (1005 metric); ROHS: NULL; Temp Range: -55°C to 125°C
L20 L21 = INDUCTOR: IND -- 4.3nH@100MHz 300mA +/-0.3nH 0402; 3D_Mechanical_Footprint_File: http://fcl.am.freescale.net/ALLEGRO/step/ind_0402.STEP; AGILE_PN: 180-10214; CAD_APPROVED: Yes; HEIGHT: 0.6mm; MFG_NAME01: Johanson Technology Inc.; MFG_PN01: LRC0402CS4N3GV001T; Package Size: 0402 (1005 Metric); ROHS: NULL; Temp Range: -55°C to +100°C
R1 = RES: RES TF 22OHM 1/20W 1% AEC-Q200 0201; AGILE_PN: 470-81170; CAD_APPROVED: Yes; HEIGHT: 0.26; MFG_NAME01: KOA SPEER; MFG_PN01: RK73H1HTTC22R0F; ROHS: Yes; Tolerance: 1%; VOLTAGE: 25V
R115 = RES: RES MF 100K 1/16W 1% 0402; AGILE_PN: 470-76240; ASSY_OPT: DNP; CAD_APPROVED: Yes; FPLIST: RC0402_25,RC0402_HD,0402_CC; HEIGHT: 0.4; MFG_NAME01: VISHAY INTERTECHNOLOGY; MFG_PN01: CRCW0402100KFKEDC; ROHS: Yes; Tolerance: 1%
R204 = RES: RES MF ZERO OHM 1/16W 5% 0402; AGILE_PN: 470-75394; ASSY_OPT: DNP; CAD_APPROVED: Yes; FPLIST: RC0402_25,RC0402_HD,RC0402_X2,0402_CC; HEIGHT: 0.45; MFG_NAME01: YAGEO AMERICA; MFG_PN01: RC0402JR-070RL; ROHS: Yes; Temp Range: -55 to +155C; Tolerance: 5%; VOLTAGE: 1/16W
R97 R116 R205 R206 = RES: RES MF 4.7K 1/16W 5% 0402; AGILE_PN: 470-75626; CAD_APPROVED: Yes; FPLIST: RC0402_25,RC0402_HD,0402_CC; HEIGHT: 0.41; MFG_NAME01: BOURNS; MFG_PN01: CR0402-JW-472GLF; ROHS: NULL; TOL: 1%; Tolerance: 5%
SH9 = RES_SHORT-3_1TO2: ZERO OHM CUT TRACE 0603 PADS; NO PART TO ORDER; AGILE_PN: 470-80018; CAD_APPROVED: Yes; HEIGHT: 0.1; ROHS: NULL; SHORTED (DEFAULT): CLOSED; SILK: PWR_RF_SW
SH24 = RES_SHORT-3_1TO2: ZERO OHM CUT TRACE 0603 PADS; NO PART TO ORDER; AGILE_PN: 470-80018; CAD_APPROVED: Yes; HEIGHT: 0.1; ROHS: NULL; SHORTED (DEFAULT): CLOSED; SILK: CTL_RF_SW
TP1 = TESTLOOP: TEST POINT PC MULTIPURPOSE LOW PROFILE PAD 40MIL DIA TH; AGILE_PN: 210-79469; CAD_APPROVED: Yes; HEIGHT: 2.54; MFG_NAME01: COMPONENTS CORPORATION; MFG_PN01: TP-103-03-T; ROHS: Yes; SILK: VDD_CORE_EXT
TP2 = TESTLOOP: TEST POINT PC MULTIPURPOSE LOW PROFILE PAD 40MIL DIA TH; AGILE_PN: 210-79469; CAD_APPROVED: Yes; HEIGHT: 2.54; MFG_NAME01: COMPONENTS CORPORATION; MFG_PN01: TP-103-03-T; ROHS: Yes; SILK: VREF_OUT
TP3 = TESTLOOP: TEST POINT PC MULTIPURPOSE LOW PROFILE PAD 40MIL DIA TH; AGILE_PN: 210-79469; CAD_APPROVED: Yes; HEIGHT: 2.54; MFG_NAME01: COMPONENTS CORPORATION; MFG_PN01: TP-103-03-T; ROHS: Yes; SILK: VDD_PA_2P4_EXT
TP4 = TESTLOOP: TEST POINT PC MULTIPURPOSE LOW PROFILE PAD 40MIL DIA TH; AGILE_PN: 210-79469; CAD_APPROVED: Yes; HEIGHT: 2.54; MFG_NAME01: COMPONENTS CORPORATION; MFG_PN01: TP-103-03-T; ROHS: Yes
TP22 = TESTLOOP: TEST POINT PC MULTI PURPOSE BLK TH; 3D_Mechanical_Footprint_File: http://fcl.am.freescale.net/ALLEGRO/step/tp_th_063.STEP; AGILE_PN: 210-79450; ASSY_OPT: DNP; CAD_APPROVED: Yes; HEIGHT: 8.13; MFG_NAME01: KEYSTONE ELECTRONICS; MFG_PN01: 5011; ROHS: NULL; Temp Range: -0 °C to +40 °C
U1 = KW47B41Z83AFTBT_HVQFN48: IC MCU 32BIT BLE 96MHz ARM CORTEX-M33 FLASH 2MB+512KB SRAM 264KB+171KB 1.71-3.6V AEC-Q100 HVQFN48; 3D_Mechanical_Footprint_File: http://fcl.am.freescale.net/ALLEGRO/step/qfn_48_0p5_7x7_5p7ep.STEP; AGILE_PN: TMP-CIP-21306; CAD_APPROVED: Yes; HEIGHT: 1.0mm; MFG_NAME01: NXP SEMICONDUCTOR; PRE_APN: 344-10102; Package Size: 7 x 7 mm; ROHS: NULL; Temp Range: -40°C to +105°C
U2 = SKYA21038_6P: IC SWITCH SPDT 0.9 to 6.0 GHz 5.5V AEC-Q100 MLPD6; 3D_Mechanical_Footprint_File: http://fcl.am.freescale.net/ALLEGRO/step/mlpd6_0p35_2ep.step; AGILE_PN: 315-81814; CAD_APPROVED: Yes; HEIGHT: 0.5MM; MFG_NAME01: SKYWORKS SOLUTIONS, INC.; ROHS: NULL; Temp Range: -40C to 105C
U21 = B9014_4P: MULTILAYER BAND PASS FILTER 2.4GHz W-LAN AEC-Q200 SMD; 3D_Mechanical_Footprint_File: http://fcl.am.freescale.net/ALLEGRO/step/filter_4_2p1x1p35_sm.STEP; AGILE_PN: TMP-CIP-17131; ASSY_OPT: DNP; CAD_APPROVED: yes; HEIGHT: 0.8MM; MFG_NAME01: TDK~SuZhou China; MFG_PN01: ZDEB202450T-0315A1; PRE_APN: 510-10034; ROHS: NULL; Temp Range: -40°C to +105°C
BMP1-BMP4 = Bumper: BUMPON CYLINDRICAL .312X.215 BLK; 3D_Mechanical_Footprint_File: http://fcl.am.freescale.net/ALLEGRO/step/bumper_rd_312mil.STEP; AGILE_PN: 280-76577; CAD_APPROVED: Yes; HEIGHT: 5.72; MFG_NAME01: 3M; MFG_PN01: SJ61A6; ROHS: NULL
BT1 = BATTERY: BATTERY HOLDER FOR CR2450N SMT; 3D_Mechanical_Footprint_File: http://fcl.am.freescale.net/ALLEGRO/step/con2_bh_cr2430.STEP; AGILE_PN: 801-76096; ASSY_OPT: DNP; CAD_APPROVED: Yes; HEIGHT: 7.7; MFG_NAME01: RENATA BATTERIES; ROHS: NULL
BT2 = BATTERY: BATTERY HOLDER CR2032 SMD; 3D_Mechanical_Footprint_File: http://fcl.am.freescale.net/ALLEGRO/step/battery_holder_2032_sm.STEP; AGILE_PN: 801-76278; CAD_APPROVED: Yes; HEIGHT: 5.5; MFG_NAME01: HARWIN INC; Package Type: SMT; ROHS: Yes; Temp Range: -40° C to +105° C; Temp_Range: -40° C to +105° C
C23 C25 C30 C41 = CAP_NP: CAP CER 10uF 16V 20% X5R 0603; AGILE_PN: 150-79092; CAD_APPROVED: Yes; FPLIST: CC0603_OV,CC0603,0603_CC; HEIGHT: 1; MFG_NAME01: YAGEO AMERICA; MFG_PN01: CC0603MRX5R7BB106; ROHS: Yes; Rated Voltage: 16V; Temp Range: -55C to +85C; Tolerance: 20%; VOLTAGE: 16V
C24 = CAP_POL: CAP TANT ESR=0.900 OHMS 10UF 10V 20% -- 3216-18; 3D_Mechanical_Footprint_File: http://fcl.am.freescale.net/ALLEGRO/step/cc3216.step; AGILE_PN: 150-75257; CAD_APPROVED: Yes; HEIGHT: 1.8; MFG_NAME01: AVX; MFG_PN01: TPSA106M010R0900; Package Size: 3216-18; Package Type: 7" T/R; ROHS: Yes; Rated Voltage: 10V; Tolerance: 20%; VOLTAGE: 10V
C26 C28 C31 C33 C35 C103-C106 C108 C111 C112 C156-C159 C161 C162 = CAP_NP: CAP CER 0.1UF 16V 10% X7R 0402; 3D_Mechanical_Footprint_File: http://fcl.am.freescale.net/ALLEGRO/step/cc0402_25.STEP; AGILE_PN: 150-75182; CAD_APPROVED: Yes; FPLIST: CC0402_25,CC0402_HD,0402_CC,CAPC0402_L; HEIGHT: 0.635mm; MFG_NAME01: KEMET; MFG_PN01: C0402C104K4RACTU; ROHS: NULL; Rated Voltage: 16V; Temp Range: -55C to +125C; Tolerance: 10%; VOLTAGE: 16V
C27 = CAP_NP: CAP CER 4.7uF 6.3V 10% X7S AEC-Q200 0603; AGILE_PN: 150-80188; ASSY_OPT: DNP; CAD_APPROVED: Yes; FPLIST: CC0603_OV,CC0603,0603_CC_NSP; HEIGHT: 1; MFG_NAME01: MURATA; MFG_PN01: GCJ188C70J475KE02D; Package Size: 0603; ROHS: Yes; Rated Voltage: 6.3V; Temp Range: -55C to +125C; Tolerance: 10%
C29 = CAP_NP: CAP CER 0.1UF 16V 10% X7R 0402; 3D_Mechanical_Footprint_File: http://fcl.am.freescale.net/ALLEGRO/step/cc0402_25.STEP; AGILE_PN: 150-75182; ASSY_OPT: DNP; CAD_APPROVED: Yes; FPLIST: CC0402_25,CC0402_HD,0402_CC,CAPC0402_L; HEIGHT: 0.635mm; MFG_NAME01: KEMET; MFG_PN01: C0402C104K4RACTU; ROHS: NULL; Rated Voltage: 16V; Temp Range: -55C to +125C; Tolerance: 10%; VOLTAGE: 16V
C32 C34 = CAP_NP: CAP CER 4.7uF 6.3V 10% X7S AEC-Q200 0603; AGILE_PN: 150-80188; CAD_APPROVED: Yes; FPLIST: CC0603_OV,CC0603,0603_CC_NSP; HEIGHT: 1; MFG_NAME01: MURATA; MFG_PN01: GCJ188C70J475KE02D; Package Size: 0603; ROHS: Yes; Rated Voltage: 6.3V; Temp Range: -55C to +125C; Tolerance: 10%
C36 = CAP_NP: CAP CER 1uF 16V 10% X7R AEC-Q200 0603; 3D_Mechanical_Footprint_File: http://fcl.am.freescale.net/ALLEGRO/step/cc0603_ov.STEP; AGILE_PN: 150-10013; CAD_APPROVED: Yes; HEIGHT: 0.95; MFG_NAME01: KEMET; MFG_PN01: C0603X105K4RACAUTO; Package Size: 0603 (1608 metric); Package Type: SMD/SMT; ROHS: NULL; Rated Voltage: 16 VDC; Temp Range: -55 to+125°C; Tolerance: 10%
C37 = CAP_NP: CAP CER 10uF 16V 20% X5R 0603; AGILE_PN: 150-79092; ASSY_OPT: DNP; CAD_APPROVED: Yes; FPLIST: CC0603_OV,CC0603,0603_CC; HEIGHT: 1; MFG_NAME01: YAGEO AMERICA; MFG_PN01: CC0603MRX5R7BB106; ROHS: Yes; Rated Voltage: 16V; Temp Range: -55C to +85C; Tolerance: 20%; VOLTAGE: 16V
C107 = CAP_NP: CAP CER 10UF 35V 20% X5R 0603; AGILE_PN: 150-79911; CAD_APPROVED: Yes; HEIGHT: 1; MFG_NAME01: MURATA; MFG_PN01: GRM188R6YA106MA73D; ROHS: Yes; Rated Voltage: 35V; Temp Range: -55C to +85C; Tolerance: 10%; VOLTAGE: 35V
C109 = CAP_POL: CAP TANT 10UF 16V 10% -- 3216-18; 3D_Mechanical_Footprint_File: http://fcl.am.freescale.net/ALLEGRO/step/cc3216.step; AGILE_PN: 150-75055; CAD_APPROVED: YES; HEIGHT: 1.8; MFG_NAME01: AVX; MFG_PN01: TAJA106K016R; Package Size: 3216-18; Package Type: 7" TAPE/REEL; ROHS: Yes; Rated Voltage: 16V; Tolerance: 10%; VOLTAGE: 16V
D1 D2 D4 D16 = DIODE_SCHTKY: DIODE SCH 1A 30V SOD123; 3D_Mechanical_Footprint_File: http://fcl.am.freescale.net/ALLEGRO/step/pmdu_sod123.STEP; AGILE_PN: 480-79681; CAD_APPROVED: Yes; HEIGHT: 0.9; MFG_NAME01: ROHM; MFG_PN01: RB160M-30TR; ROHS: Yes
D8 = DIODE: DIODE RECT SW 1A 400V SOD123W; 3D_Mechanical_Footprint_File: http://fcl.am.freescale.net/ALLEGRO/step/sod123w.STEP; AGILE_PN: 480-10151; CAD_APPROVED: YES; HEIGHT: 1.1mm; MFG_NAME01: NEXPERIA; Package Size: SOD-123W; Rated Voltage: 1.1 V @ 1 A; Temp Range: -55  to  +175C
J9 = DC_POWER_JACK_SHD: CON 3 PWR JACK RA TH 295H -- NI 98L; 3D_Mechanical_Footprint_File: http://fcl.am.freescale.net/ALLEGRO/step/con3_pwr_jack_th_pj051a.step; AGILE_PN: 210-79945; CAD_APPROVED: Yes; HEIGHT: 7.5; MFG_NAME01: CUI INC; MFG_PN01: PJ-051A; ROHS: Yes
JP1 = CONN_HDR_2X1: HDR 1X2 TH 2MM SP 300H AU 102L; AGILE_PN: 210-80456; CAD_APPROVED: Yes; HEIGHT: 7.62; Jumper (Default): 1-2; MFG_NAME01: SAMTEC; ROHS: Yes; SILK: VDD_SWITCH; Temp_Range: -55°C to +105°C
JP2 = CONN_HDR_2X2: HDR 2X2 TH 2MM CTR 217H AU 110L; 3D_Mechanical_Footprint_File: http://fcl.am.freescale.net/ALLEGRO/step/hdr202_tmm.STEP; AGILE_PN: 210-77113; CAD_APPROVED: Yes; HEIGHT: 5.33; Jumper (Default): 2-4; MFG_NAME01: SAMTEC; MFG_PN01: TMM-102-02-G-D; ROHS: Yes; SILK: V_BRD
JP3 = CONN_HDR_3X1: HDR 1X3 TH 2MM SP 295H AU 102L; AGILE_PN: 210-80201; CAD_APPROVED: Yes; HEIGHT: 7.5; Jumper (Default): 1-2; MFG_NAME01: SAMTEC; MFG_PN01: MTMM-103-06-G-S-236; ROHS: Yes; SILK: VDD_REG; Temp_Range: -55°C to +125°C
JP4 = CONN_HDR_2X1: HDR 1X2 TH 2MM SP 300H AU 102L; AGILE_PN: 210-80456; CAD_APPROVED: Yes; HEIGHT: 7.62; Jumper (Default): 1-2; MFG_NAME01: SAMTEC; ROHS: Yes; SILK: VDD_LDO_CORE; Temp_Range: -55°C to +105°C
JP6 = CONN_HDR_2X1: HDR 1X2 TH 2MM SP 300H AU 102L; AGILE_PN: 210-80456; CAD_APPROVED: Yes; HEIGHT: 7.62; Jumper (Default): 1-2; MFG_NAME01: SAMTEC; ROHS: Yes; SILK: VDD_RF; Temp_Range: -55°C to +105°C
JP7 = CONN_HDR_2X1: HDR 1X2 TH 2MM SP 300H AU 102L; AGILE_PN: 210-80456; CAD_APPROVED: Yes; HEIGHT: 7.62; Jumper (Default): 1-2; MFG_NAME01: SAMTEC; ROHS: Yes; SILK: VDD_DCDC; Temp_Range: -55°C to +105°C
JP8 = CONN_HDR_2X1: HDR 1X2 TH 2MM SP 300H AU 102L; AGILE_PN: 210-80456; CAD_APPROVED: Yes; HEIGHT: 7.62; Jumper (Default): 1-2; MFG_NAME01: SAMTEC; ROHS: Yes; SILK: VDD_IO_ABC; Temp_Range: -55°C to +105°C
JP9 = CONN_HDR_2X1: HDR 1X2 TH 2MM SP 300H AU 102L; AGILE_PN: 210-80456; CAD_APPROVED: Yes; HEIGHT: 7.62; Jumper (Default): 1-2; MFG_NAME01: SAMTEC; ROHS: Yes; SILK: VDD_ANA; Temp_Range: -55°C to +105°C
JP10 = CONN_HDR_3X1: HDR 1X3 TH 2MM SP 295H AU 102L; AGILE_PN: 210-80201; CAD_APPROVED: Yes; HEIGHT: 7.5; Jumper (Default): 1-2; MFG_NAME01: SAMTEC; MFG_PN01: MTMM-103-06-G-S-236; ROHS: Yes; SILK: V_SEC; Temp_Range: -55°C to +125°C
JS4 = CONN_HDR_2X1: HDR 1X2 TH 2MM SP 217H AU 110L, NO PART TO ORDER; AGILE_PN: 210-80699; ASSY_OPT: DNP; CAD_APPROVED: Yes; FPLIST: sh_hdr102_2mm_bottom,sh_hdr102_2mm_bottom_a; HEIGHT: 5.2; MFG_PN01: NO_PART_TO_ORDER; ROHS: Yes; SHORTED (DEFAULT): CLOSED; SILK: P5V_CAN; Temp_Range: -55°C to +125°C
R89 = RES: RES MF ZERO OHM 1/10W -- 0603; AGILE_PN: 470-80866; ASSY_OPT: DNP; CAD_APPROVED: Yes; FPLIST: RC0603_OV,RC0603,R603-X2,0603_CC; HEIGHT: 0.6; MFG_NAME01: YAGEO AMERICA; MFG_PN01: RC0603FR-070RL; ROHS: NULL; Temp Range: –55 °C to +155 °C
R200 = RES: RES MF 39K 1/16W 1% 0402; AGILE_PN: 470-77325; CAD_APPROVED: Yes; HEIGHT: 0.4; MFG_NAME01: VISHAY INTERTECHNOLOGY; MFG_PN01: CRCW040239K0FKED; ROHS: Yes; Tolerance: 1%
R201 = RES: RES MF 28K OHM 1/16W 0.1% AEC-Q200 0402; 3D_Mechanical_Footprint_File: http://fcl.am.freescale.net/ALLEGRO/step/rc0402_25.STEP; AGILE_PN: 470-83413; CAD_APPROVED: Yes; HEIGHT: 0.40; MFG_NAME01: PANASONIC; MFG_PN01: ERA-2AEB2802X; Package Size: 0402 (1005 Metric); ROHS: Yes; Temp Range: -55C to +155C; Tolerance: 0.1%
R202 = RES: RES MF 22.6K  1/16W 1% 0402; AGILE_PN: 470-30985; CAD_APPROVED: Yes; HEIGHT: 0.40; MFG_NAME01: WALSIN TECHNOLOGY CORP.; MFG_PN01: WR04X2262FTL; ROHS: Yes; Tolerance: 1%
R203 = RES: RES MF ZERO OHM 1/16W 5% 0402; AGILE_PN: 470-75394; CAD_APPROVED: Yes; FPLIST: RC0402_25,RC0402_HD,RC0402_X2,0402_CC; HEIGHT: 0.45; MFG_NAME01: YAGEO AMERICA; MFG_PN01: RC0402JR-070RL; ROHS: Yes; Temp Range: -55 to +155C; Tolerance: 5%; VOLTAGE: 1/16W
SH19 = RES_SHORT-2: ZERO OHM CUT TRACE 0603 PADS; NO PART TO ORDER; AGILE_PN: 470-80018; CAD_APPROVED: Yes; HEIGHT: 0.1; ROHS: NULL; SHORTED (DEFAULT): CLOSED
SH21-SH23 = RES_SHORT-2: ZERO OHM CUT TRACE 0402 PADS; NO PART TO ORDER; AGILE_PN: 470-76449; CAD_APPROVED: Yes; FPLIST: SH0402,SH0402_CC; HEIGHT: 0.1; ROHS: Yes; SHORTED (DEFAULT): CLOSED
TP7 = TESTLOOP: TEST POINT PAD 40MIL DIA SMT, NO PART TO ORDER; AGILE_PN: 211-76643; CAD_APPROVED: Yes; HEIGHT: 0.1; MFG_NAME01: NOTACOMPONENT; MFG_PN01: NOTACOMPONENT; ROHS: Yes
TP15-TP18 = TEST_POINT: TEST POINT RECT 2P7X4P7 MM NO PART TO ORDER; AGILE_PN: 510-78183; CAD_APPROVED: Yes; HEIGHT: 0.127; MFG_NAME01: NA; MFG_PN01: NO PART TO ORDER1; ROHS: Yes; SILK: GND
U4 = AP7361C_5P: IC VREG LDO ADJ 0.8-5.0V 1A 2.2-6V SOT89-5; 3D_Mechanical_Footprint_File: http://fcl.am.freescale.net/ALLEGRO/step/sot-89-5.step; AGILE_PN: 315-83824; CAD_APPROVED: Yes; HEIGHT: 1.6; MFG_NAME01: DIODES INC; MFG_PN01: AP7361C-Y5-13; ROHS: Yes; Temp Range: -40 to +85C; VOLTAGE: 2.2-6V
U18 = LD1117AS18: IC VREG LDO 5V 1A 20V SOT223; AGILE_PN: 315-79374; CAD_APPROVED: Yes; HEIGHT: 1.8; MFG_NAME01: ON SEMICONDUCTOR; ROHS: Yes; VOLTAGE: 5V
C110 C160 = CAP_NP: CAP CER 4700PF 50V 10% X7R 0603; AGILE_PN: 150-30078; CAD_APPROVED: Yes; FPLIST: CC0603_OV,CC0603,0603_CC; HEIGHT: 0.90; MFG_NAME01: YAGEO AMERICA; MFG_PN01: CC0603KRX7R9BB472; ROHS: Yes; Rated Voltage: 50V; Temp Range: -55C to +125C; Tolerance: 10%; VOLTAGE: 50V
J10 J11 = CONN_HDR_4X1: HDR 1X4 TH RA 100MIL SP 268H AU 124L; 3D_Mechanical_Footprint_File: http://fcl.am.freescale.net/ALLEGRO/step/con_hdr_4m_100_th_ra.STEP; AGILE_PN: 210-79929; CAD_APPROVED: Yes; HEIGHT: 6.81; MFG_NAME01: MOLEX; MFG_PN01: 0022122041; ROHS: Yes
J12 = CONN_HDR_5X1: HDR 1X5 TH 2MM SP 190H AU 138L; 3D_Mechanical_Footprint_File: http://fcl.am.freescale.net/ALLEGRO/step/hdr105_5m_79_th.STEP; AGILE_PN: 210-79735; CAD_APPROVED: Yes; HEIGHT: 4.826; MFG_NAME01: SAMTEC; ROHS: Yes; Temp Range: -55°C to +125°C
JP27 JP28 = CONN_HDR_3X1: HDR 1X3 TH 2MM SP 295H AU 102L; AGILE_PN: 210-80201; CAD_APPROVED: Yes; HEIGHT: 7.5; Jumper (Default): 1-2; MFG_NAME01: SAMTEC; MFG_PN01: MTMM-103-06-G-S-236; ROHS: Yes; Temp_Range: -55°C to +125°C
R45 R99 R118 R119 = RES: RES MF 60.4 OHM 1/8W 1% 0805; AGILE_PN: 470-77684; CAD_APPROVED: Yes; FPLIST: RC0805_OV,RC0805,0805_CC; HEIGHT: 0.6; MFG_NAME01: YAGEO AMERICA; MFG_PN01: 232273466049L; ROHS: Yes; Tolerance: 1%; VOLTAGE: 150V
R98 R100 R117 R120 = RES: RES MF ZERO OHM 1/16W 5% 0402; AGILE_PN: 470-75394; CAD_APPROVED: Yes; FPLIST: RC0603_OV,RC0603,R603-X2,0603_CC; HEIGHT: 0.45; MFG_NAME01: YAGEO AMERICA; MFG_PN01: RC0402JR-070RL; ROHS: Yes; Temp Range: -55 to +155C; Tolerance: 5%; VOLTAGE: 1/16W
U17 U20 U22 U24 = 74LVCH1T45_6P: IC XCVR 1BIT 3-STATE DUAL 1.2-5.5V XSON6; AGILE_PN: 312-80758; CAD_APPROVED: Yes; HEIGHT: 0.5; MFG_NAME01: NEXPERIA; MFG_PN01: 74LVCH1T45GM,132; ROHS: Yes; VOLTAGE: 1.2-5.5V
U19 U23 = TJA1040T_3_8P: IC XCVR CAN 5MBIT/S 4.5-5.5V AEC-Q100 SO8; AGILE_PN: 312-82239; CAD_APPROVED: Yes; HEIGHT: 1.75MM; MFG_NAME01: NXP SEMICONDUCTOR; MFG_PN01: TJA1462AT/0Z; ROHS: NULL; VOLTAGE: 4.5-5.5V

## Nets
1V8_DCDC: C5.1 C6.1 JP10.1 L1.2 R89.2
GND: BT1.2(-) BT2.2(-) C1.2 C2.2 C5.2 C6.2 C7.2 C8.2 C13.2 C14.2 C15.2 C16.2 C17.2 C18.2 C19.2 C20.2 C21.2 C22.2 C23.2 C24.2 C25.2 C26.2 C27.2 C28.2 C29.2 C30.2 C31.2 C32.2 C33.2 C34.2 C35.2 C36.2 C37.2 C38.2 C39.2 C40.2 C41.2 C103.2 C104.2 C105.2 C106.2 C107.2 C108.2 C109.2 C110.1 C111.2 C112.2 C156.2 C157.2 C158.2 C159.2 C160.1 C161.2 C162.2 C163.2 C164.2 C165.2 J7.G1(GND1) J7.G2(GND2) J7.G3(GND3) J8.G1(GND1) J8.G2(GND2) J8.G3(GND3) J9.2 J9.3 J9.SH1(SHIELD1) J9.SH2(SHIELD2) J10.4 J11.4 R201.2 R203.2 TP15.1 TP16.1 TP17.1 TP18.1 U1.19(VSS_DCDC) U1.49(E_PAD) U2.2(GND) U4.2(GND) U17.2(GND) U18.1(GND) U19.2(GND) U19.8(STB) U20.2(GND) U20.5(DIR) U21.2(GND1) U21.4(GND2) U22.2(GND) U23.2(GND) U23.8(STB) U24.2(GND) U24.5(DIR) ; also on sheet 6 7 8 9
P3V3_BATT: BT1.1(+) BT2.1(+) D2.A
P3V3_LDO: D1.C SH19.2
P5V: C23.1 D4.C D16.C R97.1 R116.1 TP7.1(Pin1) U4.1(EN) U4.4(IN) ; also on sheet 9
P5V_CAN: C103.1 C105.1 C106.1 C109.1 C111.1 C156.1 C158.1 C159.1 C161.1 D16.A JS4.1 U17.1(VCCA) U18.2(VOUT) U18.4(TAB) U19.3(VCC) U19.5(VIO) U20.1(VCCA) U22.1(VCCA) U23.3(VCC) U23.5(VIO) U24.1(VCCA)
P12V: D8.A(ANODE) J9.1 J10.3 J11.3
P12V_VBAT: C107.1 C108.1 D8.C(CATHODE) U18.3(VIN)
VBAT: C25.1 D2.C JP2.1(A1)
VDD_ANA: C34.1 JP9.2 U1.29(VDD_ANA/VREFH)
VDD_CORE: C13.1 C14.1 C16.1 C17.1 TP1.1(Pin1) U1.16(VDD_CORE_2) U1.41(VDD_CORE_1)
VDD_DCDC: C30.1 C31.1 SH22.2 U1.21(VDD_DCDC/VDD_IO_D) ; also on sheet 6
VDD_IC: JP2.2(B1) JP2.3(A2) R115.1 SH9.3 SH21.1
VDD_IO_ABC: C32.1 C33.1 JP8.2 U1.4(VDD_IO_ABC)
VDD_LDO_CORE: C35.1 C36.1 C37.1 JP4.2 U1.15(VDD_LDO_CORE)
VDD_PA_2G4: C7.1 C18.1 L2.1 R89.1 TP3.1(Pin1) U1.36(VPA_2P4GHZ)
VDD_REG: JP3.2 JP7.1 JP8.1 JP9.1 JP10.3
VDD_RF: C40.1 C41.1 SH23.2 U1.34(VDD_RF)
VDD_SWITCH: C26.1 C27.1 JP1.1 U1.6(VDD_SWITCH)
VOUT_SYS/VDD_SYS: C38.1 C39.1 C165.1 U1.22(VDD_SYS)
ADC0_A15: U1.18(PTA21/ADC0_A15/CMP0_IN2/LPSPI0_PCS3/LPUART0_RX/EWM0_OUT_b/TPM0_CH0/RF_GPO_3/RF_GPO_7/FLEXIO0_D8/RF_GPO_10/TP_HWRITE/LPUART0_CTS_b/WUU0_P5) ; also on sheet 9
ANT: L2.2 L3.1 U1.35(ANT_2P4GHZ)
ANT_RF: C1.1 L3.2 L10.1
CAN0_RX: R98.2 U1.43(PTC5/LPSPI1_PCS0/CAN0_RX/LPI2C1_SDA/TPM1_CH4/TPM2_CH1/ADC0_CONV_DATA1/RF_DTEST_2P4GHZ_5/FLEXIO0_D21/TP_DATA3/EZH_PIO11/WUU0_P22)
CAN0_TX: R100.2 U1.42(PTC4/LPSPI1_SIN/CAN0_TX/LPI2C1_SCL/TPM2_CH0/ADC0_CONV_DATA0/RF_DTEST_2P4GHZ_4/FLEXIO0_D20/TP_DATA2/EZH_PIO10/WUU0_P10)
CAN1_RX: JP27.3 R117.2
CAN1_TX: JP28.3 R120.2
CAN_DIR: R97.2 R116.2 U17.5(DIR) U22.5(DIR)
CAN_HI_1: J10.1 R99.2 U19.7(CANH)
CAN_HI_2: J11.1 R118.2 U23.7(CANH)
CAN_LO_1: J10.2 R45.1 U19.6(CANL)
CAN_LO_2: J11.2 R119.1 U23.6(CANL)
CAN_RX_1: U17.3(A) U19.4(RXD)
CAN_RX_2: U22.3(A) U23.4(RXD)
CAN_TX_1: U19.1(TXD) U20.3(A)
CAN_TX_2: U23.1(TXD) U24.3(A)
DCDC_LX: L1.1 R1.1 U1.20(DCDC_LX)
EXTAL32K: U1.28(PTD5/EXTAL32K/LPTMR1_ALT2) ; also on sheet 6
EXTAL_RF: U1.33(EXTAL) ; also on sheet 6
FL_USB_5V0: D4.A JS4.2 ; also on sheet 7
GPO0: J12.1 U1.13(PTA18/CMP1_IN1/LPSPI0_SOUT/LPUART0_CTS_b/LPI2C0_SDA/TPM0_CH3/RF_GPO_0/RF_FPGA_IN1/LPUART0_RX/SPC0_LPREQ/WUU0_P20)
GPO1: J12.2 U1.14(PTA19/CMP1_IN0/ATX1/LPSPI0_SCK/LPUART0_RTS_b/LPI2C0_SCL/TPM0_CH2/RF_GPO_1/RF_FPGA_IN2/NVM_SDO/EZH_PIO1/WUU0_P4)
GPO2: U1.17(PTA20/ADC0_A14/CMP0_IN3/LPSPI0_PCS2/LPUART0_TX/EWM0_IN/TPM0_CH1/RF_GPO_2/FLEXIO0_D7/TP_LOAD_EN/LPUART0_RTS_b) ; also on sheet 9
I2C1_SCL: R206.2 U1.3(PTB5/NVM_TM1/LPSPI1_PCS2/LPUART1_RTS_b/LPI2C1_SCL/I3C0_SCL/TRGMUX0_OUT0/ADC0_CONV_CLK/RF_DTEST_2P4GHZ_12/FLEXIO0_D31/TP_HREADY/EZH_PIO25) ; also on sheet 6 9
I2C1_SDA: R205.2 U1.2(PTB4/NVM_TM0/LPSPI1_PCS3/LPUART1_CTS_b/LPI2C1_SDA/I3C0_SDA/TRGMUX0_IN0/ADC0_CONV_DATA7/RF_DTEST_2P4GHZ_11/FLEXIO0_D30/TP_HRESP/EZH_PIO24/WUU0_P15) ; also on sheet 6 9
LPSPI_PCS0: U1.46(PTB0/ADC0_B10/LPSPI1_PCS0/CAN1_RX/TPM1_CH0/ADC0_CONV_DATA3/RF_DTEST_2P4GHZ_7/FLEXIO0_D26/TP_ADDR0/EZH_PIO20/WUU0_P13) ; also on sheet 6 9
LPSPI_SCK: U1.48(PTB2/ADC0_B12/LPSPI1_SCK/LPUART1_TX/TPM1_CH2/ADC0_CONV_DATA5/RF_DTEST_2P4GHZ_9/FLEXIO0_D28/TP_ADDR2/EZH_PIO22) ; also on sheet 6 9
LPSPI_SIN: U1.47(PTB1/ADC0_B11/LPSPI1_SIN/CAN1_TX/TPM1_CH1/ADC0_CONV_DATA4/RF_DTEST_2P4GHZ_8/FLEXIO0_D27/TP_ADDR1/EZH_PIO21) ; also on sheet 6 9
LPSPI_SOUT: U1.1(PTB3/ADC0_B13/LPSPI1_SOUT/LPUART1_RX/TPM1_CH3/ADC0_CONV_DATA6/RF_DTEST_2P4GHZ_10/FLEXIO0_D29/TP_ADDR3/EZH_PIO23/WUU0_P14) ; also on sheet 6 9
MLINK_3V3: R204.1 ; also on sheet 7 8 9
P_VDD_SWITCH: JP1.2 JP3.1 SH21.2
RF_50: C2.1 C3.1 L10.2 U21.1(IN)
RF_A: C96.1 C97.1 U2.1(OUTPUT1)
RF_ANT_1: ANT10.1 C97.2
RF_ANT_2: ANT20.1 C99.2
RF_B: C98.1 C99.1 U2.3(OUTPUT2)
RF_GPO_4: J12.4 SH9.1 SH24.3 U1.24(PTD1/ADC0_B5/SPC0_LPREQ/NMI_b/RF_GPO_4/RF_GPO_7/LPTMR2_TRIG_OUT_b/RF_UART_RX/RF_FPGA_IN3)
RF_GPO_5: J12.5 R115.2 SH24.1 U1.25(PTD2/ADC0_A6/LPTMR0_ALT3/TAMPER0/RF_GPO_5/TPM2_CH0/LPTMR1_TRIG_OUT_b/RF_UART_TX/RF_FPGA_IN4)
RF_GPO_6: U1.26(PTD3/ADC0_B6/LPTMR1_ALT3/TAMPER1/RF_GPO_6/TPM2_CH1/TRGMUX0_IN2/LPTMR0_TRIG_OUT_b/RF_UART_CTS_b/RF_FPGA_IN5) ; also on sheet 9
RST_TGTMCU_B: U1.23(PTD0/ADC0_A5/RESET_b) ; also on sheet 6 8 9
SW_50: C3.2 U2.5(INPUT) U21.3(OUT)
SWD_CLK: U1.9(PTA1/CMP1_OUT/LPUART0_RTS_b/RF_GPO_10/TPM0_CH5/FLEXIO0_D1/SWD_CLK/TP_HCLK) ; also on sheet 8
SWD_DIO: U1.8(PTA0/CMP0_OUT/LPUART0_CTS_b/RF_GPO_11/TPM0_CH4/FLEXIO0_D0/SWD_DIO/WUU0_P0) ; also on sheet 8
SWITCH_WAKEUP_B: TP4.1(Pin1) U1.5(~{SWITCH_WAKEUP})
SWO/BOOT_CFG: U1.10(PTA4/ADC0_A10/CMP0_IN0/ATX0/RF_PLL_TEST_CLK/RF_GPO_9/TPM0_CLKIN/TRACE_SWO/FLEXIO0_D4/BOOT_CONFIG/WUU0_P2/RF_XTAL_OUT_ENABLE) ; also on sheet 8
TMP1_CH0: C21.1 U1.37(PTC0/LPSPI1_PCS2/CAN0_TX/I3C0_SDA/TPM1_CH0/SEC_RX/LPI2C1_SCL/RF_DTEST_2P4GHZ_0/FLEXIO0_D16/RF_UART_CTS_b/EZH_PIO8/WUU0_P7) ; also on sheet 6 9
TMP1_CH5: U1.44(PTC6/ADC0_A8/LPSPI1_PCS1/TPM1_CH5/ADC0_CONV_DATA2/RF_DTEST_2P4GHZ_6/FLEXIO0_D22/CAN1_RX/WUU0_P11) ; also on sheet 6
UART0_RX: U1.11(PTA16/ADC0_A12/NVM_TM2/LPSPI0_PCS0/EWM0_OUT_b/LPI2C0_SCLS/TPM0_CH4/LPUART0_RX/RF_GPO_8/RF_FPGA_IN0/FLEXIO0_D5/EZH_PIO0/WUU0_P19/RF_NOT_ALLOWED) ; also on sheet 9
UART0_TX: U1.12(PTA17/ADC0_A13/NVM_TM3/LPSPI0_SIN/EWM0_IN/LPI2C0_SDAS/TPM0_CH5/LPUART0_TX/RF_GPO_7/RF_GPO_8/FLEXIO0_D6/TP_HTRANS/RF_EXT_XTAL_REQUEST/RF_GPO_7/WUU0_P3/RF_NOT_ALLOWED) ; also on sheet 9
UART1_RX: JP27.1 ; also on sheet 9
UART1_RX/CAN1_RX: C163.1 JP27.2 U1.39(PTC2/LPSPI1_SOUT/LPUART1_RX/LPI2C1_SCLS/TPM1_CH2/RF_UART_RX/I3C0_PUR/RF_DTEST_2P4GHZ_2/FLEXIO0_D18/TP_DATA0/CAN1_RX/WUU0_P9)
UART1_TX: JP28.1 ; also on sheet 9
UART1_TX/CAN1_TX: C164.1 JP28.2 U1.40(PTC3/LPSPI1_SCK/LPUART1_TX/LPI2C1_SDAS/TPM1_CH3/RF_UART_TX/RF_DTEST_2P4GHZ_3/FLEXIO0_D19/TP_DATA1/CAN1_TX)
V_BRD: C104.1 C112.1 C157.1 C162.1 JP2.4(B2) R205.1 R206.1 SH19.1 U17.6(VCCB) U20.6(VCCB) U22.6(VCCB) U24.6(VCCB) ; also on sheet 6 8 9
V_LDO_OUT: C24.1 D1.A R200.1 U4.5(OUT)
V_SEC: JP4.1 JP6.1 JP10.2
VOUT_SWITCH: C28.1 C29.1 JP3.3 U1.7(VOUT_SWITCH)
VREF_OUT: C15.1 TP2.1(Pin1) U1.30(VREF_OUT/VREFO)
WUU0_P8: C22.1 U1.38(PTC1/LPSPI1_PCS3/CAN0_RX/I3C0_SCL/TPM1_CH1/SEC_TX/LPI2C1_SDA/RF_DTEST_2P4GHZ_1/FLEXIO0_D17/RF_UART_RTS_b/EZH_PIO9/WUU0_P8) ; also on sheet 6
WUU0_P12/NMI_b: J12.3 U1.45(PTC7/TRGMUX0_IN3/TRGMUX0_OUT3/SFA0_CLK/TPM1_CLKIN/TPM2_CLKIN/CLKOUT/RF_DTEST_2P4GHZ_13/FLEXIO0_D23/NMI_b/CAN1_TX/WUU0_P12/NMI_b/RF_NOT_ALLOWED) ; also on sheet 6 9
XTAL32K: U1.27(PTD4/XTAL32K/LPTMR0_ALT2/TAMPER2/RF_UART_RTS_b) ; also on sheet 6
XTAL_OUT: TP22.1(Pin1) U1.31(XTAL_OUT)
XTAL_RF: U1.32(XTAL) ; also on sheet 6
N24355935: C8.1 R1.2
N24374306: JP7.2 SH22.1
N24374396: JP6.2 SH23.1
N24441947: C19.1 C20.1 R204.2 SH9.2 U2.6(VDD)
N24444926: C98.2 J8.1(CTR)
N24516334: SH24.2 U2.4(VCTL)
N24687861: R200.2 R201.1 R202.1 U4.3(ADJ)
N24687954: R202.2 R203.1
N24732897: C96.2 J7.1(CTR)
N24840090: R98.1 U17.4(B)
N24840097: C110.2 R45.2 R99.1
N24840123: R100.1 U20.4(B)
N24840158: R117.1 U22.4(B)
N24840165: C160.2 R118.1 R119.2
N24840191: R120.1 U24.4(B)
N25240377: ANT20.3 L21.2
N25240378: ANT10.2 L20.1
N25240379: ANT20.2 L21.1
N25240380: ANT10.3 L20.2

Not connected (* = marked no-connect by the designer): BMP1 1(NC)*; BMP2 1(NC)*; BMP3 1(NC)*; BMP4 1(NC)*

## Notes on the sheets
sheet 1
- CAN0 - PHY #1
- PTC5
- CAN0
- PTC4
- CAN1 - PHY #2
- CAN1
- RF GPO HDR
- UART1 - CAN1 SELECTOR
- PTC2
- GPO0
- DTEST_13
- GPO1
- GPO4/GPO7
- GPO5
- PTC3
- LANT & COEX SIGNALS
sheet 2
- Revisions & Change Log
- Table of Contents
- Rev
- Description
- Date
- Approved
- X1
- First Release
- 03/20/24
- M.B - K.P.
- 01.
- TITLE PAGE
- X2
- RF GPO Header - JP26
- 04/04/24
- K.P.
- 02.
- BLOCK DIAGRAM
- RST LED circuit update
- RF SW CTL update
- Antennas symbol changed
- RF SW VDD update
- 03.
- KW47B41Z MCU
- Pi-array for antenna updated
- Pullup added for RF SW CTL
- 04.
- PWR MANAGEMENT
- Components for DCDC peaks
  removed or updated for
  zero-ohm cut traces SH21-SH23
- 05.
- LED, MEMORY, XTAL
- RF switch powered VDD_IC
- 04/10/24
- 06.
- MCU Link
- LANT/GPIO updated on JP26/JP23
- 07.
- MCU Link SWD
- J7 and J8 update BOM
- 04/25/24
- J4 and J5 update BOM
- 05/02/24
- 08.
- MLink IO, MikroBus
- J7/J8 SMA footprint update
- VDD_DCDC net fix
- 09.
- CAN, RF GPO
- Block diagram
- X3
- C9-C12, L11-L12 removed
- 05/24/24
- K.P.
- L20&L21 values to 4.7nH
- C21&C22 moved to PTC0/PTC1
- JP13,JP14,JP27,JP28 replaced
  for PCB shunt headers.
- 2nd CAN PHY support
- 05/27/24
- X4
- Adjustable LDO - U4 for 1.8V
- 05/28/24
- K.P.
- support
- A
- Prototype Release
- 06/20/24
- K.P.
- B
- Tracking Changes List
- 01/07/24
- K.P.
- Prototype II Release
- 02/19/24
- K.P.
- C
- C165 added to VOUT_SYS
  R32 added to EXTAL_RF
  Block diagram updated
- 06/27/25
- M. B.
- D
- Production Release
- 09/10/25
- K.P.
- KW47-LOC
  "Bluetooth Low Energy Channel Sounding"
- (KW47 LOCalization kit)
- BL Secure Connected Edge
- Connectivity
- To ease your board design, Please refer to the nxp.com web and NXP
  community article ' The best way to build a PCB first time right '
sheet 3
- NOTES
- 1. Unless Otherwise Specified:
- All resistors are in ohms, 5%, 1/8 Watt
- All capacitors are in uF, 20%, 50V
- All voltages are DC
- All polarized capacitors are aluminum electrolytic
- 2. Interrupted lines coded with the same letter or letter
      combinations are electrically connected.
- 3. Device type number is for reference only. The number
      varies with the manufacturer.
- 4. Special signal usage:
- _B Denotes - Active-Low Signal
- <> or [] Denotes - Vectored Signals
- 5. Interpret diagram in accordance with American
  National Standards Institute specifications, current
  revision, with the exception of logic block symbology.
- NOTES
- This Color is for User Notes
- This Color is for CAD/LAY Notes
- This Color is custom Shield Notes
- This Color is for Silk
- This Color is for DNP components
- Target MCU: KW47 p[3]
  Debug MCULink: LPC55S69  p[6]
- Jumper Table
- REF DES
- JUMPER(DEFAULT)
- PAGE NAME
- JP1,JP3,JP4,JP6,JP7,JP8,JP9,
  JP10
- 1-2
- 04. PWR MANAGEMENT
- JP2
- 2-4
- 04. PWR MANAGEMENT
- JP12,JP21,JP22
- OPEN
- 06. MCU Link
- JP18,JP25
- 1-2
- 07. MCU Link SWD
- JP17
- OPEN
- 07. MCU Link SWD
- JP23,JP24
- 1-2
- 08. MLink IO, MikroBus
- JP27,JP28
- 1-2
- 09. CAN, RF GPO
- DNP Table
- Short Table
- REF DES
- ASSY_OPT
- PAGE NAME
- REF DES
- SHORTED(DEFAULT)
- PAGE NAME
- C16,C21,C22,C38,C96,C98,C163,
  C164,J7,J8,R115,R204,TP22,U21
- DNP
- 03. KW47B41Z MCU
- SH9,SH24
- CLOSED
- 03. KW47B41Z MCU
- JS4,SH19,SH21,SH22,SH23
- CLOSED
- 04. PWR MANAGEMENT
- BT1,C27,C29,C37,JS4,R89
- DNP
- 04. PWR MANAGEMENT
- JS1,JS2,JS3,JS14
- CLOSED
- 05. LED, MEMORY, XTAL
- C49,C50,JS1,JS2,JS3,JS14,R9,
  R10,R11,R15,R17,R18,R21
- DNP
- 05. LED, MEMORY, XTAL
- SH15,SH20
- CLOSED
- 07. MCU Link SWD
- JS5,JS6,JS10,JS11,SH1,SH2,
  SH3,SH4,SH5,SH6,SH8,SH10,
  SH11,SH12,SH13,SH14
- CLOSED
- 08. MLink IO, MikroBus
- C77,C78,J4,R41,R42,U9
- DNP
- 06. MCU Link
- C113,R65,R66
- DNP
- 07. MCU Link SWD
- JS5,JS6
- DNP
- 08. MLink IO, MikroBus
sheet 4
- DCDC Inductor
- Reference Design Area
- CAD note: Place
  C13 & C14 caps
  close to pin16
- CAD note: Place
  C16 & C17 caps
  close to pin41
- (to DCDC_LX inductor)
- MLZ2012A1R0WTD25
  L1
- VDD_SYS = 1.71V -2.75V
- CAD note: Place ALL caps close to MCU
- Reference Design Area
- SWD_DIO
- SWD_CLK
- SWD
- SWO/BOOT_CONF
- LPUART0_RX
- LPUART0_TX
- RF_GPO_0
- LPUART0
- RF_GPO_1
- RF_GPO_2
- ADC0_A15
- LPSPI1_PCS0
- LPSPI1_SIN
- LPSPI1_SK
- LPSPI1
- LPSPI1_SOUT
- I2C1_SDA/LPSPI1_PCS3
- I2C1_SCL/LPSPI1_PCS2
- LPI2C1
- TMP1_CH0/LED_RED
- WUU0_P8/USER_PB
- LPUART1_RX
- LPUART1_TX
- LPUART1
- CAN0_TX
- CAN0_RX
- CAN0
- TMP1_CH5/LED_YEL
- WUU0_P12/NMI_b/USER_PB
- RST
- RF_SW_PWR/RF_GPO_4
- RST
- RF_SW_CTL/RF_GPO_5
- RF_GPO_6
- Reference Design Area
- RF
- PTD1
- VCO leakage decoupling capacitors.
- i
- VDD_PA_2G4 enable +10dBm RF output
- LQG15HZ15NJ02D
  L2 AUTO PART
- RF SWITCH
- CAD NOTE:
  C96 and C97
  share pin1
- ANTENNA A
- CAD Note: Keep ANT
  trace short  as
  possible
- ANTENNA B
- CAD NOTE:
  C98 and C99
  share pin1
- Reference Design Area
- PTD2
- LQG15HS1N3S02
  L3  AUTO PART
- LQG15HS1N2S02
  L10 AUTO PART
- PTD1
- GCM1555C1H150GA16D
  C3 AUTO PART - TBD
- GJM1555C1H3R3CB01
  C1 AUTO PART
- GJM1555C1H1R0CB01
  C2 AUTO PART
- CAD Note:
- 50 ohm controlled
  impedence line
- RF matching  components
  recommended for your first
  prototype and to fine tune
  moving to the final production
  platform
- VDD (Pin 6)
- VCTL (Pin 4)
- INPUT TO OUTPUT1 PATH
- INPUT TO OUTPUT2 PATH
- 1
- 0
- Isolation
- Insertion loss
- Keep the same length of
  the RF signals
  RFA and RFB in the layout
- 1
- 1
- Insertion loss
- Isolation
sheet 5
- POWER MANAGEMENT
- SECONDARY
  OPTION
- COIN CELL
  HOLDER
- Vout= Vref*(1+R200/Rx)
- Rx= 1/[(1/R201)+(1/R202)]
- Vref=0.8V
- CAD note: BT2 should be should be overlapped w/BT1
           Use secondary (bottom) side for placement
- Vout= 3.3V
- For 1.8V DNP R203
- CAN Power
- IN CIRCUIT TEST
  GND PROBING
- External 12V
- Note: PCB Shunt on Bottom Side
- BUMPON added to each bottom side corner
- Reference Design Area
- KW47 POWER CONFIGURATION
- V_SEC
   JP10
- DEFAULT CONFIG :
- DCDC Mode
- CAD note: Place ALL caps close to MCU
- Dec Caps inside the Reference Design Area
- DCDC Mode
- 1-2
- VDD_SWITCH (JP1) : 1-2
- V_BRD (JP2) : 2-4
- VDD_REG (JP3) : 1-2
- VDD_LDO_CORE (JP4): 1-2
- VDD_RF (JP6) : 1-2
- VDD_DCDC (JP7) : 1-2
- LDO Mode
- 2-3
- VDD_ANA (JP9) : 1-2
- VDD_IO_ABC (JP8) : 1-2
- i
- TP3 enables VDD_PA_2G4 for +10dBm RF output
- (from DCDC_LX inductor)
- (VDD_IO_D)
- CAD note: Place ALL caps close to MCU
- Dec Caps inside the Reference Design Area
- CAD note: Place ALL caps close to MCU
- Dec Caps inside the Reference Design Area
- CAD note: Place ALL caps close to MCU
- Dec Caps inside the Reference Design Area
- 6.3V
- JP4, JP6, JP7 & JP8 used for current measurements
